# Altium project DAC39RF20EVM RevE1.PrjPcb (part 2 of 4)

## Sheet Power LDO N1p8V Analog.SchDoc: DAC Analog -1.8V
size 431 x 279 mm; Date: Not shown in title block; ApprovedBy: Not shown in title block; CheckedBy: Not shown in title block; Author: Not shown in title block; CompanyName: Not shown in title block; Engineer: Not shown in title block; Organization: Not shown in title block; Address1: Not shown in title block; Address2: Not shown in title block; Address3: Not shown in title block; Address4: Not shown in title block; DocumentNumber: 1; Revision: Use project parameter SCH_Rev; SheetNumber: 7; SheetTotal: 21; PageSetup: Record=PageOptions¦CenterHorizontal=True¦CenterVertical=True¦PrintScale=1.00¦XCorrection=1.00¦YCorrection=1.00¦PrintKind=0¦BorderSize=5000000¦LeftOffset=0¦BottomOffset=0¦Orientation=2¦PaperLength=1000¦PaperWidth=1000¦Scale=100¦PaperSource=15¦PrintQuality=600¦MediaType=1¦DitherType=10¦PaperKind=Letter¦PrintScaleMode=1
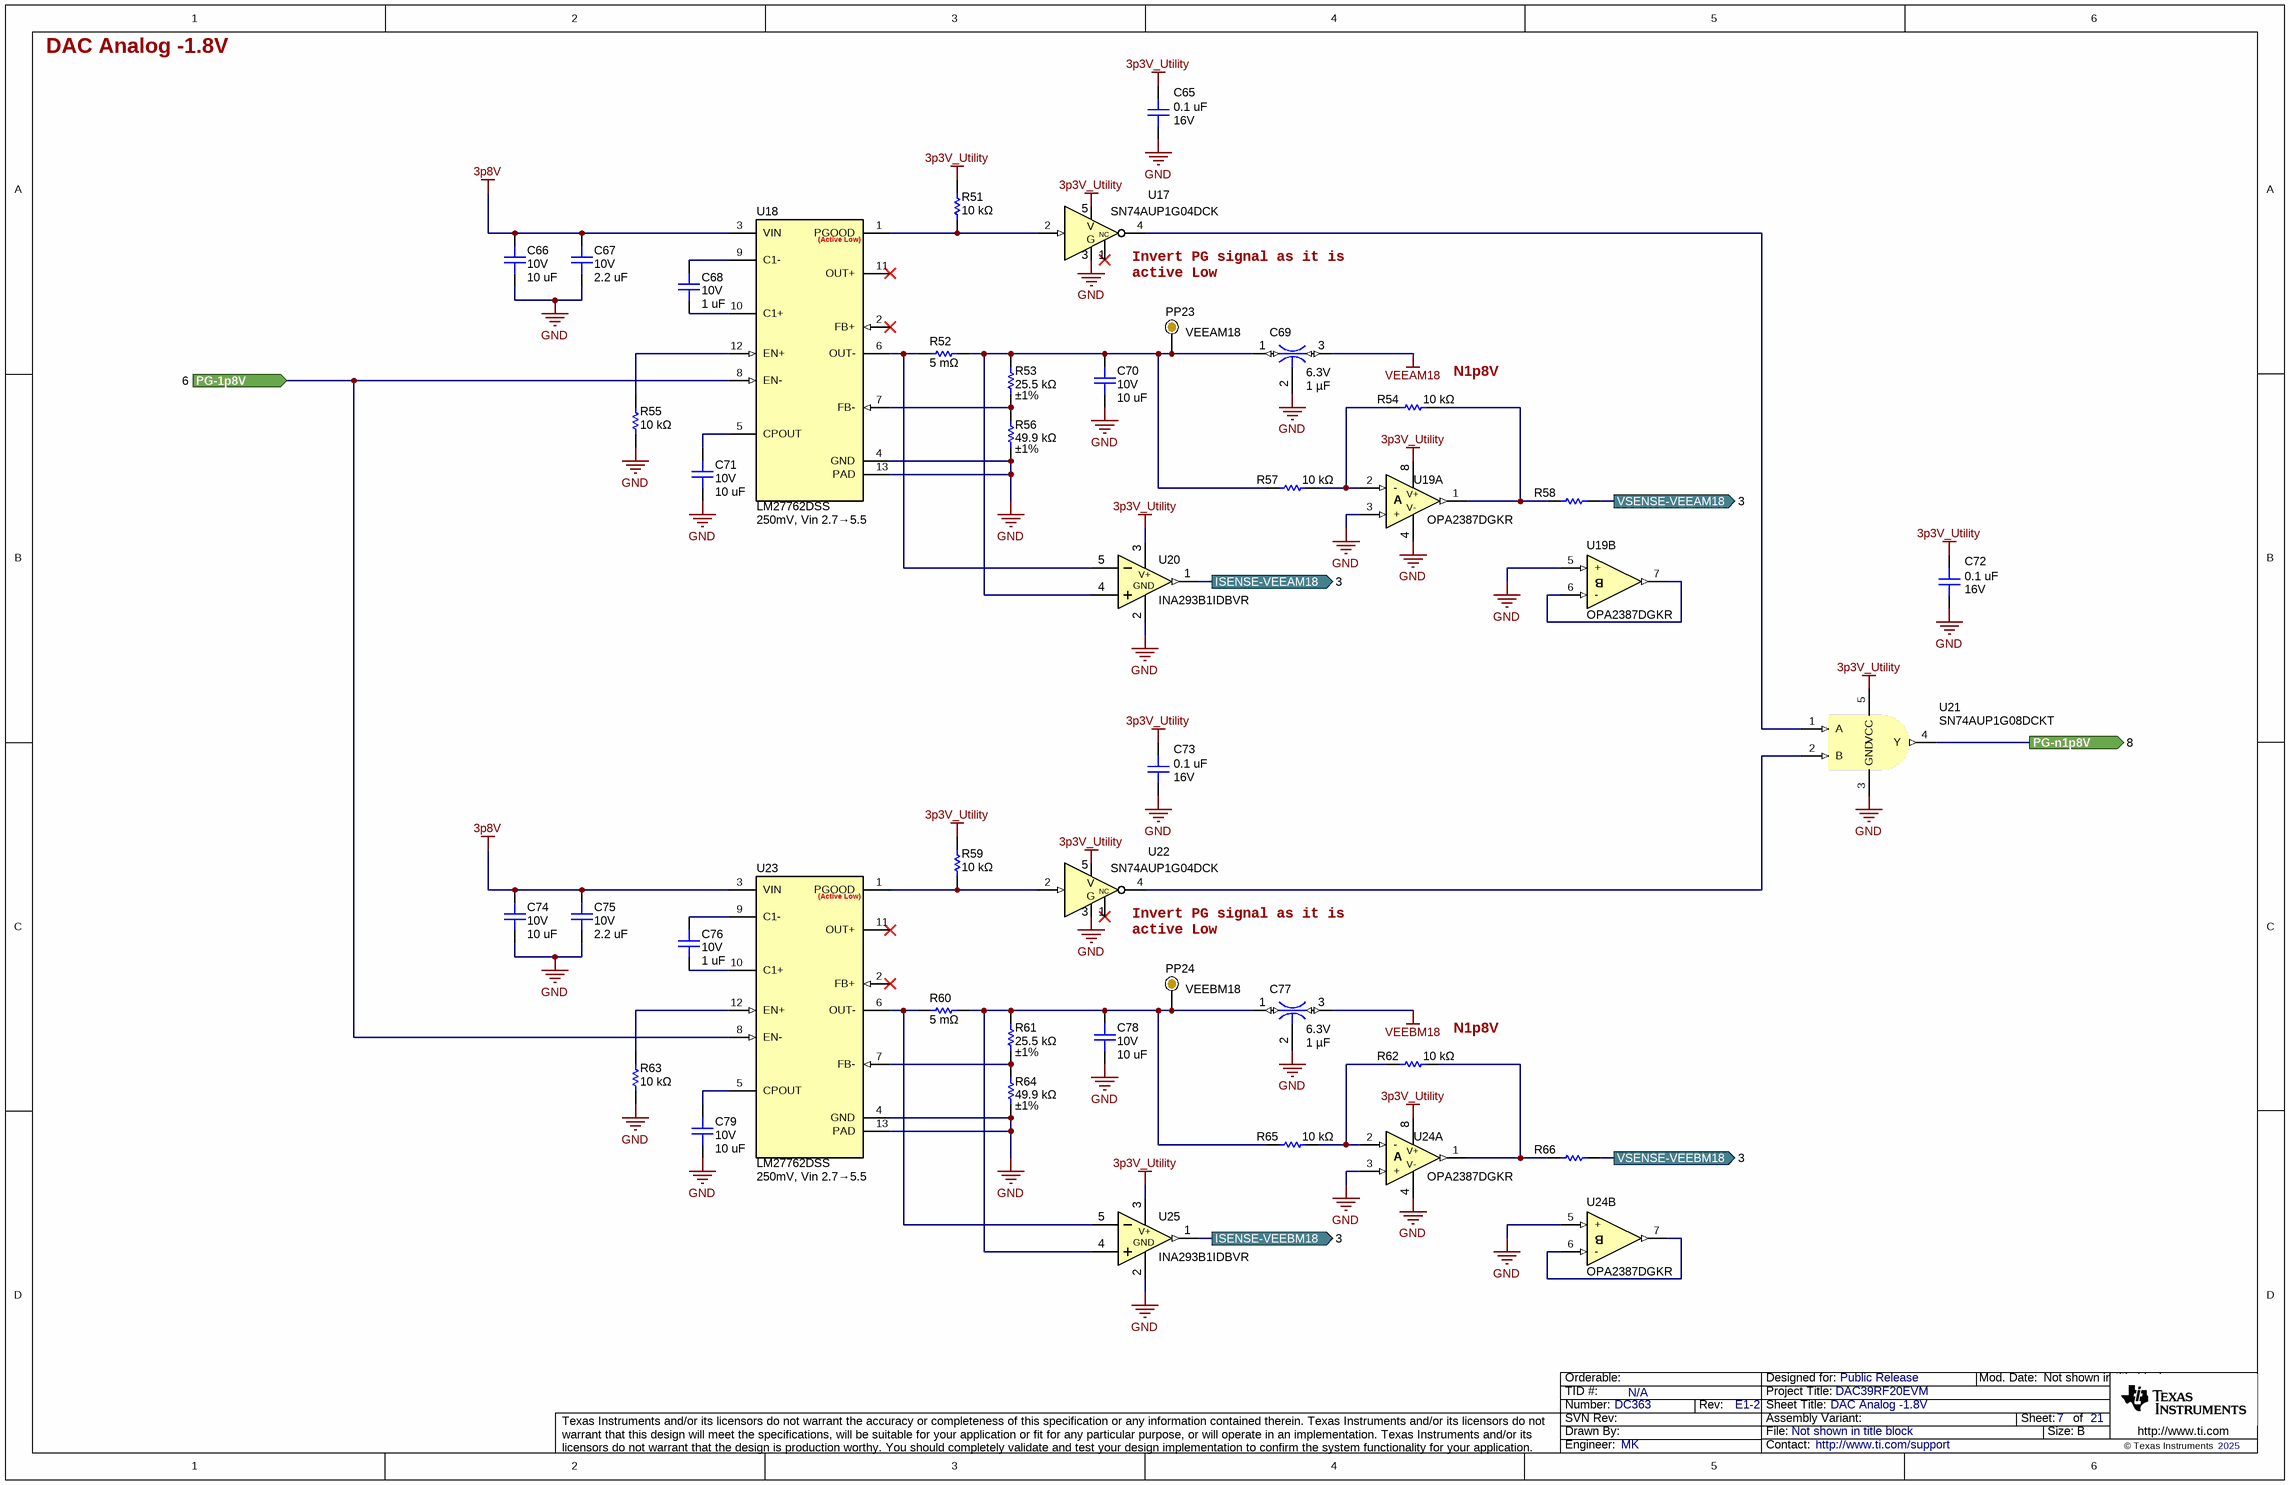
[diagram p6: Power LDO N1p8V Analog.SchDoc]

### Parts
C65  value 0.1 uF  Voltage - Rated: 16V  [0201_cap]  (hidden comment: GRM033Z71C104KE14J)
C66  value 10 uF  Voltage - Rated: 10V  [0603L_cap]  (hidden comment: 0603ZD106KAT2A)
C67  value 2.2 uF  Voltage - Rated: 10V  [0402L_cap]  (hidden comment: C1005X5R1A225K050BC)
C68  value 1 uF  Voltage - Rated: 10V  [0201_cap]  (hidden comment: GRM033R61A105ME44D)
C69  value 1 µF  Voltage - Rated: 6.3V  [NFM18PC]  (hidden comment: NFM18PC105R0J3D)
C70  value 10 uF  Voltage - Rated: 10V  [0603L_cap]  (hidden comment: 0603ZD106KAT2A)
C71  value 10 uF  Voltage - Rated: 10V  [0603L_cap]  (hidden comment: 0603ZD106KAT2A)
C72  value 0.1 uF  Voltage - Rated: 16V  [0201_cap]  (hidden comment: GRM033Z71C104KE14J)
C73  value 0.1 uF  Voltage - Rated: 16V  [0201_cap]  (hidden comment: GRM033Z71C104KE14J)
C74  value 10 uF  Voltage - Rated: 10V  [0603L_cap]  (hidden comment: 0603ZD106KAT2A)
C75  value 2.2 uF  Voltage - Rated: 10V  [0402L_cap]  (hidden comment: C1005X5R1A225K050BC)
C76  value 1 uF  Voltage - Rated: 10V  [0201_cap]  (hidden comment: GRM033R61A105ME44D)
C77  value 1 µF  Voltage - Rated: 6.3V  [NFM18PC]  (hidden comment: NFM18PC105R0J3D)
C78  value 10 uF  Voltage - Rated: 10V  [0603L_cap]  (hidden comment: 0603ZD106KAT2A)
C79  value 10 uF  Voltage - Rated: 10V  [0603L_cap]  (hidden comment: 0603ZD106KAT2A)
PP23  Text1: VEEAM18  [ProbePoint_TH_40mil]  (hidden comment: Probe Point)  (no BOM)
PP24  Text1: VEEBM18  [ProbePoint_TH_40mil]  (hidden comment: Probe Point)  (no BOM)
R51  value 10 kΩ  [0402L]  (hidden comment: ERJ-H2RF1002X)
R52  value 5 mΩ  [CCS0603FLxLxx]  (hidden comment: CSS0603FT5L00)
R53  value 25.5 kΩ  Tolerance: ±1%  [0402L]  (hidden comment: ERJ-2RKF2552X)
R54  value 10 kΩ  [0201]  (hidden comment: ERJ-U01F1002C)
R55  value 10 kΩ  [0402L]  (hidden comment: ERJ-H2RF1002X)
R56  value 49.9 kΩ  Tolerance: ±1%  [0402L]  (hidden comment: ERJ-2RKF4992X)
R57  value 10 kΩ  [0201]  (hidden comment: ERJ-U01F1002C)
R58  ERJ-1GNF1000C  [0201]  (value not drawn)
R59  value 10 kΩ  [0402L]  (hidden comment: ERJ-H2RF1002X)
R60  value 5 mΩ  [CCS0603FLxLxx]  (hidden comment: CSS0603FT5L00)
R61  value 25.5 kΩ  Tolerance: ±1%  [0402L]  (hidden comment: ERJ-2RKF2552X)
R62  value 10 kΩ  [0201]  (hidden comment: ERJ-U01F1002C)
R63  value 10 kΩ  [0402L]  (hidden comment: ERJ-H2RF1002X)
R64  value 49.9 kΩ  Tolerance: ±1%  [0402L]  (hidden comment: ERJ-2RKF4992X)
R65  value 10 kΩ  [0201]  (hidden comment: ERJ-U01F1002C)
R66  ERJ-1GNF1000C  [0201]  (value not drawn)
U17  SN74AUP1G04DCK  [DCK0005A]
U18  LM27762DSS  Text1: 250mV, Vin 2.7→5.5  [DSS0012B]
U19  OPA2387DGKR  [DGK0008A]  (parts A,B of 2)
U20  INA293B1IDBVR  [DBV0005A]
U21  SN74AUP1G08DCKT  [DCK0005A]
U22  SN74AUP1G04DCK  [DCK0005A]
U23  LM27762DSS  Text1: 250mV, Vin 2.7→5.5  [DSS0012B]
U24  OPA2387DGKR  [DGK0008A]  (parts A,B of 2)
U25  INA293B1IDBVR  [DBV0005A]

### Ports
ISENSE-VEEAM18 (out, see 3), ISENSE-VEEBM18 (out, see 3), PG-1p8V (in, see 6), PG-n1p8V (out, see 8), VSENSE-VEEAM18 (out, see 3), VSENSE-VEEBM18 (out, see 3)

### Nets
3p3V_Utility: C65.2 C72.2 C73.2 R51.2 R59.2 U17.5(VCC) U19.8(V+) U20.3(V+) U21.5(VCC) U22.5(VCC) U24.8(V+) U25.3(V+)
3p8V: C66.2 C67.2 C74.2 C75.2 U18.3(VIN) U23.3(VIN)
GND: C65.1 C66.1 C67.1 C69.2 C70.1 C71.1 C72.1 C73.1 C74.1 C75.1 C77.2 C78.1 C79.1 R55.1 R56.1 R63.1 R64.1 U17.3(GND) U18.4(GND) U18.13(PAD) U19.3(+) U19.4(GND) U19.5(+) U20.2(GND) U21.3(GND) U22.3(GND) U23.4(GND) U23.13(PAD) U24.3(+) U24.4(GND) U24.5(+) U25.2(GND)
VEEAM18: C69.3
VEEBM18: C77.3
ISENSE-VEEAM18: U20.1(OUT) ; port ISENSE-VEEAM18
ISENSE-VEEBM18: U25.1(OUT) ; port ISENSE-VEEBM18
PG-1p8V: U18.8(EN-) U23.8(EN-) ; port PG-1p8V
PG-n1p8V: U21.4(Y) ; port PG-n1p8V
VSENSE-VEEAM18: R58.2 ; port VSENSE-VEEAM18
VSENSE-VEEBM18: R66.2 ; port VSENSE-VEEBM18
NetC68_1: C68.1 U18.10(C1+)
NetC68_2: C68.2 U18.9(C1-)
NetC69_1: C69.1 C70.2 PP23.1 R52.2 R53.2 R57.1 U20.4(VIN+)
NetC71_2: C71.2 U18.5(CPOUT)
NetC76_1: C76.1 U23.10(C1+)
NetC76_2: C76.2 U23.9(C1-)
NetC77_1: C77.1 C78.2 PP24.1 R60.2 R61.2 R65.1 U25.4(VIN+)
NetC79_2: C79.2 U23.5(CPOUT)
NetR51_1: R51.1 U17.2(A) U18.1(PGOOD)
NetR52_1: R52.1 U18.6(OUT-) U20.5(VIN-)
NetR53_1: R53.1 R56.2 U18.7(FB-)
NetR54_1: R54.1 R57.2 U19.2(-)
NetR54_2: R54.2 R58.1 U19.1(A)
NetR55_2: R55.2 U18.12(EN+)
NetR59_1: R59.1 U22.2(A) U23.1(PGOOD)
NetR60_1: R60.1 U23.6(OUT-) U25.5(VIN-)
NetR61_1: R61.1 R64.2 U23.7(FB-)
NetR62_1: R62.1 R65.2 U24.2(-)
NetR62_2: R62.2 R66.1 U24.1(A)
NetR63_2: R63.2 U23.12(EN+)
NetU17_4: U17.4(Y) U21.1(A)
NetU19_6: U19.6(-) U19.7(B)
NetU21_2: U21.2(B) U22.4(Y)
NetU24_6: U24.6(-) U24.7(B)

Not connected (* = marked no-connect by the designer): U17 1(NC)*; U18 2(FB+)* 11(OUT+)*; U22 1(NC)*; U23 2(FB+)* 11(OUT+)*

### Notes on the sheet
- (near U17) Invert PG signal as it is active Low
- (near R54) N1p8V
- (near U22) Invert PG signal as it is active Low
- (near R62) N1p8V

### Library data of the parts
C65 C72 C73 = capcc09325: MLCC 0.1UF 16V X7R 0603; Manufacturer: Murata Electronics; SizeZ_mm: 0.33; SizeX_mm: 0.6; SizeY_mm: 0.3; CompType: Capacitor Ceramic; Tolerance: ±10%
C66 C70 C71 C74 C78 C79 = capcc03657: CAP CER 10UF 10V X5R 0603; Manufacturer: KYOCERA AVX; CompType: Capacitor Ceramic; Tolerance: ±10%; SizeX_mm: 1.6; SizeY_mm: 0.81; SizeZ_mm: 0.94
C67 C75 = capcc03112: CAP CER 2.2UF 10V X5R 0402; Manufacturer: TDK Corporation; CompType: Capacitor Ceramic; Tolerance: ±10%; SizeX_mm: 1; SizeY_mm: 0.5; SizeZ_mm: 0.55
C68 C76 = capcc09264: CAP CER 1UF 10V X5R 0201; Manufacturer: Murata Electronics; CompType: Capacitor Ceramic; Tolerance: ±20%; SizeX_mm: 0.6; SizeY_mm: 0.3; SizeZ_mm: 0.33
C69 C77 = dcp00009: CAP FEEDTHRU 1UF 20% 6.3V 0603; Manufacturer: Murata Electronics; CompType: Feed Thru Cap; Current: 4 A; DCR: 10 mΩ; SizeX_mm: 1.6; SizeY_mm: 0.8; SizeZ_mm: 0.7
PP23 PP24 = Probe Point: Probe Point that can be used in lue of a test point; UniqueID: cmp00025
R51 R55 R59 R63 = RSMD040200316: RES 10K OHM 1% 1/10W 0402; Manufacturer: Panasonic Electronic Components; CompType: Resistor SMD; Power (Watts): 0.1W, 1/10W; Temperature Coefficient: ±100ppm/°C; SizeX_mm: 1; SizeY_mm: 0.5; SizeZ_mm: 0.4
R52 R60 = OtherRs00006: RES 0.005 OHM 1% 1/3W 0603; Manufacturer: Stackpole Electronics Inc; CompType: Resistor SMD Sense; Power (Watts): 0.333W, 1/3W; Temperature Coefficient: ±50ppm/°C; SizeX_mm: 1.6; SizeY_mm: 0.8; SizeZ_mm: 0.65
R53 R61 = RSMD040201705: RES SMD 25.5K OHM 1% 1/10W 0402; Manufacturer: Panasonic Electronic Components; CompType: Resistor SMD; Power (Watts): 0.1W, 1/10W; Temperature Coefficient: ±100ppm/°C; SizeX_mm: 1; SizeY_mm: 0.5; SizeZ_mm: 0.4
R54 R57 R62 R65 = RSMD020100735: RES 10K OHM 1% 1/20W 0201 SMD; Manufacturer: Panasonic Electronic Components; CompType: Resistor SMD; Power (Watts): 0.05W, 1/20W; Temperature Coefficient: ±200ppm/°C
R56 R64 = RSMD040202910: RES SMD 49.9K OHM 1% 1/10W 0402; Manufacturer: Panasonic Electronic Components; CompType: Resistor SMD; Power (Watts): 0.1W, 1/10W; Temperature Coefficient: ±100ppm/°C; SizeX_mm: 1; SizeY_mm: 0.5; SizeZ_mm: 0.4
R58 R66 = RSMD020100289: RES SMD 100 OHM 1% 1/20W 0201; Manufacturer: Panasonic Electronic Components; Value: 100 Ω; CompType: Resistor SMD; Power (Watts): 0.05W, 1/20W; Temperature Coefficient: ±200ppm/°C
U17 U22 = cmp00128: Single Bus Inverting Buffer Gate; Manufacturer: Texas Instruments
U18 U23 = cmp00189: Low-Noise Positive- and Negative-Output Charge Pump With Integrated LDO; Manufacturer: Texas Instruments; CompType: Switcher
U19 U24 = OPA2387DGKR: Manufacturer: Texas Instruments; CompType: Op-amp
U20 U25 = INA293B1IDBV: INA293 High-Voltage, High Bandwidth, Unidirectional, 110-V Common-Mode, Current-Sense Amplifier, DBV0005A (SOT-23-5); Manufacturer: Texas Instruments; Alternate PartNumber: INA293B1IDBVT; SizeX_mm: 2.8; SizeArea_mm2: 8.12; SizeAreaWB_mm2: 14.82; AEC Qualified: N; AEC Category: Q200; SizeZ_mm: 1.45; CompType: IC; SizeY_mm: 2.9
U21 = cmp00268: SN74AUP1G08 Low-Power Single 2-Input Positive-AND Gate; Manufacturer: Texas Instruments

## Sheet Power LDO 0p8V Analog.SchDoc: DAC Analog 0.8V & 1V
size 431 x 279 mm; Date: Not shown in title block; ApprovedBy: Not shown in title block; CheckedBy: Not shown in title block; Author: Not shown in title block; CompanyName: Not shown in title block; Engineer: Not shown in title block; Organization: Not shown in title block; Address1: Not shown in title block; Address2: Not shown in title block; Address3: Not shown in title block; Address4: Not shown in title block; DocumentNumber: 1; Revision: Use project parameter SCH_Rev; SheetNumber: 8; SheetTotal: 21; PageSetup: Record=PageOptions¦CenterHorizontal=True¦CenterVertical=True¦PrintScale=1.00¦XCorrection=1.00¦YCorrection=1.00¦PrintKind=0¦BorderSize=5000000¦LeftOffset=0¦BottomOffset=0¦Orientation=2¦PaperLength=1000¦PaperWidth=1000¦Scale=100¦PaperSource=15¦PrintQuality=600¦MediaType=1¦DitherType=10¦PaperKind=Letter¦PrintScaleMode=1
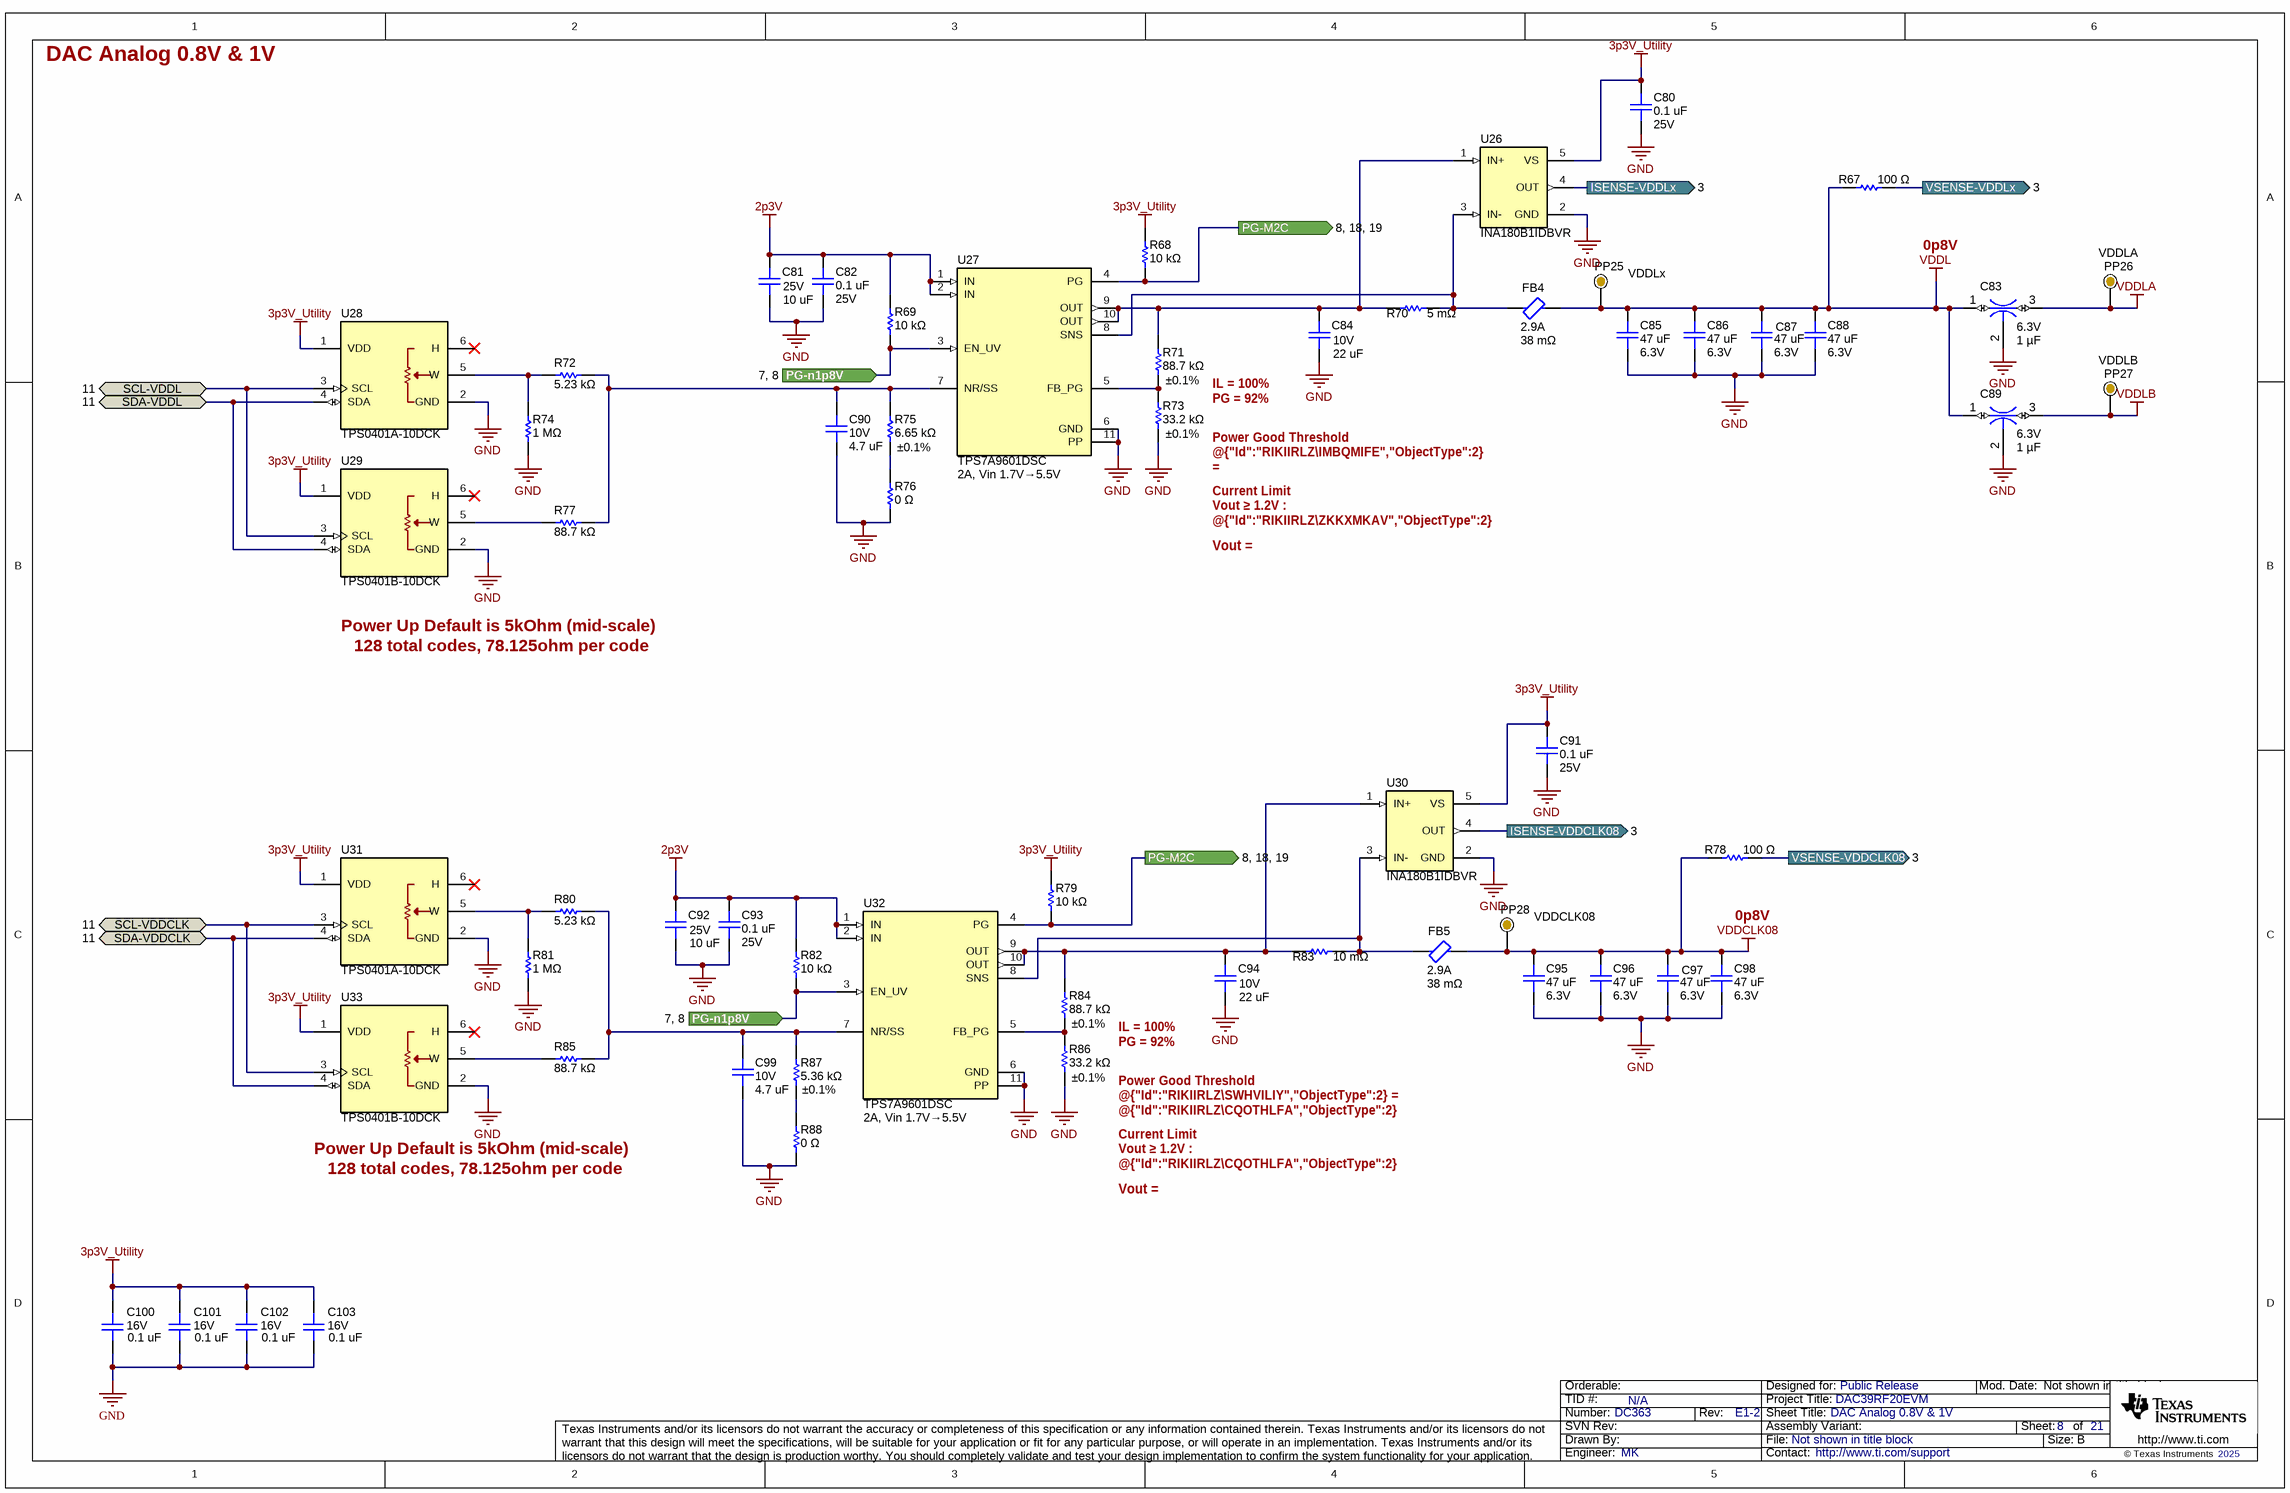
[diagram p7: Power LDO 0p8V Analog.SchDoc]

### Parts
C80  value 0.1 uF  Voltage - Rated: 25V  [0402L_cap]  (hidden comment: GRT155R71E104KE01J)
C81  value 10 uF  Voltage - Rated: 25V  [0805L_cap]  (hidden comment: C2012X7S1E106K125AC)
C82  value 0.1 uF  Voltage - Rated: 25V  [0402L_cap]  (hidden comment: GRT155R71E104KE01J)
C83  value 1 µF  Voltage - Rated: 6.3V  [NFM18PC]  (hidden comment: NFM18PC105R0J3D)
C84  value 22 uF  Voltage - Rated: 10V  [0805L_cap]  (hidden comment: C2012X7S1A226M125AC)
C85  value 47 uF  Voltage - Rated: 6.3V  [0603L_cap]  (hidden comment: GRM188R60J476ME15D)
C86  value 47 uF  Voltage - Rated: 6.3V  [0603L_cap]  (hidden comment: GRM188R60J476ME15D)
C87  value 47 uF  Voltage - Rated: 6.3V  [0603L_cap]  (hidden comment: GRM188R60J476ME15D)
C88  value 47 uF  Voltage - Rated: 6.3V  [0603L_cap]  (hidden comment: GRM188R60J476ME15D)
C89  value 1 µF  Voltage - Rated: 6.3V  [NFM18PC]  (hidden comment: NFM18PC105R0J3D)
C90  value 4.7 uF  Voltage - Rated: 10V  [0402L_cap]  (hidden comment: C1005X5R1A475K050BE)
C91  value 0.1 uF  Voltage - Rated: 25V  [0402L_cap]  (hidden comment: GRT155R71E104KE01J)
C92  value 10 uF  Voltage - Rated: 25V  [0805L_cap]  (hidden comment: C2012X7S1E106K125AC)
C93  value 0.1 uF  Voltage - Rated: 25V  [0402L_cap]  (hidden comment: GRT155R71E104KE01J)
C94  value 22 uF  Voltage - Rated: 10V  [0805L_cap]  (hidden comment: C2012X7S1A226M125AC)
C95  value 47 uF  Voltage - Rated: 6.3V  [0603L_cap]  (hidden comment: GRM188R60J476ME15D)
C96  value 47 uF  Voltage - Rated: 6.3V  [0603L_cap]  (hidden comment: GRM188R60J476ME15D)
C97  value 47 uF  Voltage - Rated: 6.3V  [0603L_cap]  (hidden comment: GRM188R60J476ME15D)
C98  value 47 uF  Voltage - Rated: 6.3V  [0603L_cap]  (hidden comment: GRM188R60J476ME15D)
C99  value 4.7 uF  Voltage - Rated: 10V  [0402L_cap]  (hidden comment: C1005X5R1A475K050BE)
C100  value 0.1 uF  Voltage - Rated: 16V  [0201_cap]  (hidden comment: C0603X5R1C104K030BC)
C101  value 0.1 uF  Voltage - Rated: 16V  [0201_cap]  (hidden comment: C0603X5R1C104K030BC)
C102  value 0.1 uF  Voltage - Rated: 16V  [0201_cap]  (hidden comment: C0603X5R1C104K030BC)
C103  value 0.1 uF  Voltage - Rated: 16V  [0201_cap]  (hidden comment: C0603X5R1C104K030BC)
FB4  Current: 2.9A  DCR: 38 mΩ  [1206L]  (hidden comment: BLM31KN601SN1L)
FB5  Current: 2.9A  DCR: 38 mΩ  [1206L]  (hidden comment: BLM31KN601SN1L)
PP25  Text1: VDDLx  [ProbePoint_TH_40mil]  (hidden comment: Probe Point)  (no BOM)
PP26  Text1: VDDLA  [ProbePoint_TH_40mil]  (hidden comment: Probe Point)  (no BOM)
PP27  Text1: VDDLB  [ProbePoint_TH_40mil]  (hidden comment: Probe Point)  (no BOM)
PP28  Text1: VDDCLK08  [ProbePoint_TH_40mil]  (hidden comment: Probe Point)  (no BOM)
R67  value 100 Ω  [0201]  (hidden comment: ERJ-1GNF1000C)
R68  value 10 kΩ  [0402L]  (hidden comment: ERJ-2RKF1002X)
R69  value 10 kΩ  [0402L]  (hidden comment: ERJ-2RKF1002X)
R70  value 5 mΩ  [CCS0603FLxLxx]  (hidden comment: CSS0603FT5L00)
R71  value 88.7 kΩ  Tolerance: ±0.1%  [0402L]  (hidden comment: ERA-2AEB8872X)
R72  value 5.23 kΩ  [0402L]  (hidden comment: ERA-2ARB5231X)
R73  value 33.2 kΩ  Tolerance: ±0.1%  [0402L]  (hidden comment: ERA-2AEB3322X)
R74  value 1 MΩ  [0402L]  (hidden comment: ERJ-PA2F1004X)
R75  value 6.65 kΩ  Tolerance: ±0.1%  [0402L]  (hidden comment: ERA-2AEB6651X)
R76  value 0 Ω  [0402L]  (hidden comment: ERJ-U020R00X)
R77  value 88.7 kΩ  [0402L]  (hidden comment: ERA-2AEB8872X)
R78  value 100 Ω  [0201]  (hidden comment: ERJ-1GNF1000C)
R79  value 10 kΩ  [0402L]  (hidden comment: ERJ-2RKF1002X)
R80  value 5.23 kΩ  [0402L]  (hidden comment: ERA-2ARB5231X)
R81  value 1 MΩ  [0402L]  (hidden comment: ERJ-PA2F1004X)
R82  value 10 kΩ  [0402L]  (hidden comment: ERJ-2RKF1002X)
R83  value 10 mΩ  [CCS0603FLxLxx]  (hidden comment: CSS0603FT10L0)
R84  value 88.7 kΩ  Tolerance: ±0.1%  [0402L]  (hidden comment: ERA-2AEB8872X)
R85  value 88.7 kΩ  [0402L]  (hidden comment: ERA-2AEB8872X)
R86  value 33.2 kΩ  Tolerance: ±0.1%  [0402L]  (hidden comment: ERA-2AEB3322X)
R87  value 5.36 kΩ  Tolerance: ±0.1%  [0402L]  (hidden comment: ERA-2AEB5361X)
R88  value 0 Ω  [0402L]  (hidden comment: ERJ-U020R00X)
U26  INA180B1IDBVR  [DBV0005A]
U27  TPS7A9601DSC  Text1: 2A, Vin 1.7V→5.5V  [DRC0010J]
U28  TPS0401A-10DCK  [DCK0006A]
U29  TPS0401B-10DCK  [DCK0006A]
U30  INA180B1IDBVR  [DBV0005A]
U31  TPS0401A-10DCK  [DCK0006A]
U32  TPS7A9601DSC  Text1: 2A, Vin 1.7V→5.5V  [DRC0010J]
U33  TPS0401B-10DCK  [DCK0006A]

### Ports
ISENSE-VDDCLK08 (out, see 3), ISENSE-VDDLx (out, see 3), PG-M2C (out, see 8, 18, 19), PG-n1p8V (in, see 7, 8), SCL-VDDCLK (bidir, see 11), SCL-VDDL (bidir, see 11), SDA-VDDCLK (bidir, see 11), SDA-VDDL (bidir, see 11), VSENSE-VDDCLK08 (out, see 3), VSENSE-VDDLx (out, see 3)

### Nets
2p3V: C81.2 C82.2 C92.2 C93.2 R69.2 R82.2 U27.1(IN) U27.2(IN) U32.1(IN) U32.2(IN)
3p3V_Utility: C80.2 C91.2 C100.1 C101.1 C102.1 C103.1 R68.2 R79.2 U26.5(VS) U28.1(VDD) U29.1(VDD) U30.5(VS) U31.1(VDD) U33.1(VDD)
GND: C80.1 C81.1 C82.1 C83.2 C84.1 C85.1 C86.1 C87.1 C88.1 C89.2 C90.1 C91.1 C92.1 C93.1 C94.1 C95.1 C96.1 C97.1 C98.1 C99.1 C100.2 C101.2 C102.2 C103.2 R73.1 R74.2 R76.1 R81.2 R86.1 R88.1 U26.2(GND) U27.6(GND) U27.11(PP) U28.2(GND) U29.2(GND) U30.2(GND) U31.2(GND) U32.6(GND) U32.11(PP) U33.2(GND)
VDDCLK08: C95.2 C96.2 C97.2 C98.2 FB5.2 PP28.1 R78.1
VDDL: C83.1 C85.2 C86.2 C87.2 C88.2 C89.1 FB4.2 PP25.1 R67.1
VDDLA: C83.3 PP26.1
VDDLB: C89.3 PP27.1
ISENSE-VDDCLK08: U30.4(OUT) ; port ISENSE-VDDCLK08
ISENSE-VDDLx: U26.4(OUT) ; port ISENSE-VDDLx
PG-M2C: R68.1 R79.1 U27.4(PG) U32.4(PG) ; port PG-M2C
PG-n1p8V: R69.1 R82.1 U27.3(EN_UV) U32.3(EN_UV) ; port PG-n1p8V
SCL-VDDCLK: U31.3(SCL) U33.3(SCL) ; port SCL-VDDCLK
SCL-VDDL: U28.3(SCL) U29.3(SCL) ; port SCL-VDDL
SDA-VDDCLK: U31.4(SDA) U33.4(SDA) ; port SDA-VDDCLK
SDA-VDDL: U28.4(SDA) U29.4(SDA) ; port SDA-VDDL
VSENSE-VDDCLK08: R78.2 ; port VSENSE-VDDCLK08
VSENSE-VDDLx: R67.2 ; port VSENSE-VDDLx
NetC84_2: C84.2 R70.1 R71.2 U26.1(IN+) U27.9(OUT) U27.10(OUT)
NetC90_2: C90.2 R72.1 R75.2 R77.2 U27.7(NR/SS)
NetC94_2: C94.2 R83.1 R84.2 U30.1(IN+) U32.9(OUT) U32.10(OUT)
NetC99_2: C99.2 R80.1 R85.2 R87.2 U32.7(NR/SS)
NetFB4_1: FB4.1 R70.2 U26.3(IN-) U27.8(SNS)
NetFB5_1: FB5.1 R83.2 U30.3(IN-) U32.8(SNS)
NetR71_1: R71.1 R73.2 U27.5(FB_PG)
NetR72_2: R72.2 R74.1 U28.5(W)
NetR75_1: R75.1 R76.2
NetR77_1: R77.1 U29.5(W)
NetR80_2: R80.2 R81.1 U31.5(W)
NetR84_1: R84.1 R86.2 U32.5(FB_PG)
NetR85_1: R85.1 U33.5(W)
NetR87_1: R87.1 R88.2

Not connected (* = marked no-connect by the designer): U28 6(H)*; U29 6(H)*; U31 6(H)*; U33 6(H)*

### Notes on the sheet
- 0p8V
- IL = 100%
  PG = 92%
- Power Good Threshold
  @{"Id":"RIKIIRLZ\IMBQMIFE","ObjectType":2} = @{"Id":"RIKIIRLZ\ZKKXMKAV","ObjectType":2} * (VOUT/0.2*K-1)
  K = PG % Threshold
- Current Limit
  Vout ≥ 1.2V :    @{"Id":"RIKIIRLZ\ZKKXMKAV","ObjectType":2} = 0.2V/16µA = 12.4kΩ
  0.4V≤Vout<1.2V : @{"Id":"RIKIIRLZ\ZKKXMKAV","ObjectType":2}  = 0.2V/6µA = 33.2k Ω
- Vout = (@{"Id":"RIKIIRLZ\SPHKWSGB","ObjectType":2} + @{"Id":"RIKIIRLZ\QDQZCBMS","ObjectType":2}) *150µA
- Power Up Default is 5kOhm (mid-scale)
- 128 total codes, 78.125ohm per code
- Power Good Threshold
  @{"Id":"RIKIIRLZ\SWHVILIY","ObjectType":2} = @{"Id":"RIKIIRLZ\CQOTHLFA","ObjectType":2} * (VOUT/0.2*K-1)
  K = PG % Threshold
- Current Limit
  Vout ≥ 1.2V :    @{"Id":"RIKIIRLZ\CQOTHLFA","ObjectType":2} = 0.2V/16µA = 12.4kΩ
  0.4V≤Vout<1.2V : @{"Id":"RIKIIRLZ\CQOTHLFA","ObjectType":2}  = 0.2V/6µA = 33.2k Ω
- Vout = (@{"Id":"RIKIIRLZ\LLIXUJIG","ObjectType":2} + @{"Id":"RIKIIRLZ\LXJCPRKC","ObjectType":2}) *150µA

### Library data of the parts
C80 C82 C91 C93 = capcc09401: CAP CER 0.1UF 25V X7R 0402; Manufacturer: Murata; CompType: Capacitor Ceramic; Tolerance: ±10%; SizeX_mm: 1; SizeY_mm: 0.5; SizeZ_mm: 0.7
C81 C92 = capcc03511: CAP CER 10UF 25V X7S 0805; Manufacturer: TDK Corporation; CompType: Capacitor Ceramic; Tolerance: ±10%; SizeX_mm: 2; SizeY_mm: 1.25; SizeZ_mm: 1.5
C83 C89 = dcp00009: as C69 on sheet Power LDO N1p8V Analog
C84 C94 = capcc09395: CAP CER 22UF 10V X7S 0805; Manufacturer: TDK Corporation; CompType: Capacitor Ceramic; Tolerance: ±20%; SizeX_mm: 2; SizeY_mm: 1.25; SizeZ_mm: 1.45
C85-C88 C95-C98 = GRM188R60J476ME15D: CAP CER 47UF 6.3V X5R 0603; Manufacturer: Murata; CompType: Capacitor Ceramic; Tolerance: ±20%; SizeX_mm: 1.6; SizeY_mm: 0.81; SizeZ_mm: 0.9
C90 C99 = capcc03139: CAP CER 4.7UF 10V X5R 0402; Manufacturer: TDK Corporation; CompType: Capacitor Ceramic; Tolerance: ±10%; SizeX_mm: 1; SizeY_mm: 0.5; SizeZ_mm: 0.7
C100-C103 = capcc01389: CAP CER 0.1UF 16V X5R 0201; Manufacturer: TDK Corporation; SizeZ_mm: 0.33; SizeY_mm: 0.3; CompType: Capacitor Ceramic; SizeX_mm: 0.6; Tolerance: ±10%
FB4 FB5 = dcp00613: FERRITE BEAD 600 OHM 1206 1LN; Manufacturer: Murata Electronics; Impedance: 600 Ω
PP25-PP28 = Probe Point: as PP23 on sheet Power LDO N1p8V Analog
R67 R78 = RSMD020100289: RES SMD 100 OHM 1% 1/20W 0201; Manufacturer: Panasonic Electronic Components; CompType: Resistor SMD; Power (Watts): 0.05W, 1/20W; Temperature Coefficient: ±200ppm/°C
R68 R69 R79 R82 = RSMD040200314: RES SMD 10K OHM 1% 1/10W 0402; Manufacturer: Panasonic Electronic Components; CompType: Resistor SMD; Power (Watts): 0.1W, 1/10W; Temperature Coefficient: ±100ppm/°C; SizeX_mm: 1; SizeY_mm: 0.5; SizeZ_mm: 0.4
R70 = OtherRs00006: as R52 on sheet Power LDO N1p8V Analog
R71 R77 R84 R85 = RSMD040203878: RES SMD 88.7KOHM 0.1% 1/16W 0402; Manufacturer: Panasonic Electronic Components; CompType: Resistor SMD; Power (Watts): 0.063W, 1/16W; Temperature Coefficient: ±25ppm/°C; SizeX_mm: 1; SizeY_mm: 0.5; SizeZ_mm: 0.4
R72 R80 = RSMD040202949: RES SMD 5.23KOHM 0.1% 1/16W 0402; Manufacturer: Panasonic Electronic Components; CompType: Resistor SMD; Power (Watts): 0.063W, 1/16W; Temperature Coefficient: ±10ppm/°C; SizeX_mm: 1; SizeY_mm: 0.5; SizeZ_mm: 0.4
R73 R86 = RSMD040202236: RES SMD 33.2KOHM 0.1% 1/16W 0402; Manufacturer: Panasonic Electronic Components; CompType: Resistor SMD; Power (Watts): 0.063W, 1/16W; Temperature Coefficient: ±25ppm/°C; SizeX_mm: 1; SizeY_mm: 0.5; SizeZ_mm: 0.4
R74 R81 = RSMD040200022: RES SMD 1M OHM 1% 1/5W 0402; Manufacturer: Panasonic Electronic Components; CompType: Resistor SMD; Power (Watts): 0.2W, 1/5W; Temperature Coefficient: ±100ppm/°C; SizeX_mm: 1; SizeY_mm: 0.5; SizeZ_mm: 0.4
R75 = RSMD040203275: RES SMD 6.65KOHM 0.1% 1/16W 0402; Manufacturer: Panasonic Electronic Components; CompType: Resistor SMD; Power (Watts): 0.063W, 1/16W; Temperature Coefficient: ±25ppm/°C; SizeX_mm: 1; SizeY_mm: 0.5; SizeZ_mm: 0.4
R76 R88 = RSMD040200004: RES 0 OHM JUMPER 0402 SMD; Manufacturer: Panasonic Electronic Components; CompType: Resistor SMD; Power (Watts): 0.1W, 1/10W; Temperature Coefficient: -100/ +600ppm/°C; SizeX_mm: 1; SizeY_mm: 0.5; SizeZ_mm: 0.4
R83 = OtherRs00003: RES 0.01 OHM 1% 1/3W 0603; Manufacturer: Stackpole Electronics Inc; CompType: Resistor SMD Sense; Power (Watts): 0.333W, 1/3W; Temperature Coefficient: ±50ppm/°C; SizeX_mm: 1.6; SizeY_mm: 0.8; SizeZ_mm: 0.65
R87 = RSMD040202954: RES SMD 5.36KOHM 0.1% 1/16W 0402; Manufacturer: Panasonic Electronic Components; CompType: Resistor SMD; Power (Watts): 0.063W, 1/16W; Temperature Coefficient: ±25ppm/°C; SizeX_mm: 1; SizeY_mm: 0.5; SizeZ_mm: 0.4
U26 U30 = INA180B1IDBVR: 26V, 350kHz current sense amplifier; Manufacturer: Texas Instruments; Alt PartNumber: INA180B1IDBVT; CompType: Current Amplifier
U27 U32 = cmp00446: 2-A, ultra-low noise ultra-high PSRR RF voltage regulator; PartNumber: TPS7A9601DSCR; Manufacturer: Texas Instruments; CompType: LDO
U28 U31 = cmp00230: 128-tap single-channel digital potentiometer (digipot) with I2C interface (address 0101110); Alternate PartNumber: TPL0401A-10DCKT; Manufacturer: Texas Instruments; SymbolCreator: Altium; SizeArea_mm2: 4.2; U/M: EA; SizeAreaWB_mm2: 9.3
U29 U33 = cmp00231: 128-tap single-channel digital potentiometer (digipot) with I2C interface (address 0111110); Alternate PartNumber: TPL0401A-10DCKT; Manufacturer: Texas Instruments; SymbolCreator: Altium; SizeArea_mm2: 4.2; U/M: EA; SizeAreaWB_mm2: 9.3

## Sheet Power LMK.SchDoc: LMK 3.3V Power
size 431 x 279 mm; Date: Not shown in title block; ApprovedBy: Not shown in title block; CheckedBy: Not shown in title block; Author: Not shown in title block; CompanyName: Not shown in title block; Engineer: Not shown in title block; Organization: Not shown in title block; Address1: Not shown in title block; Address2: Not shown in title block; Address3: Not shown in title block; Address4: Not shown in title block; DocumentNumber: 1; Revision: Use project parameter SCH_Rev; SheetNumber: 9; SheetTotal: 21; PageSetup: Record=PageOptions¦CenterHorizontal=True¦CenterVertical=True¦PrintScale=1.00¦XCorrection=1.00¦YCorrection=1.00¦PrintKind=0¦BorderSize=5000000¦LeftOffset=0¦BottomOffset=0¦Orientation=2¦PaperLength=1000¦PaperWidth=1000¦Scale=100¦PaperSource=15¦PrintQuality=600¦MediaType=1¦DitherType=10¦PaperKind=Letter¦PrintScaleMode=1
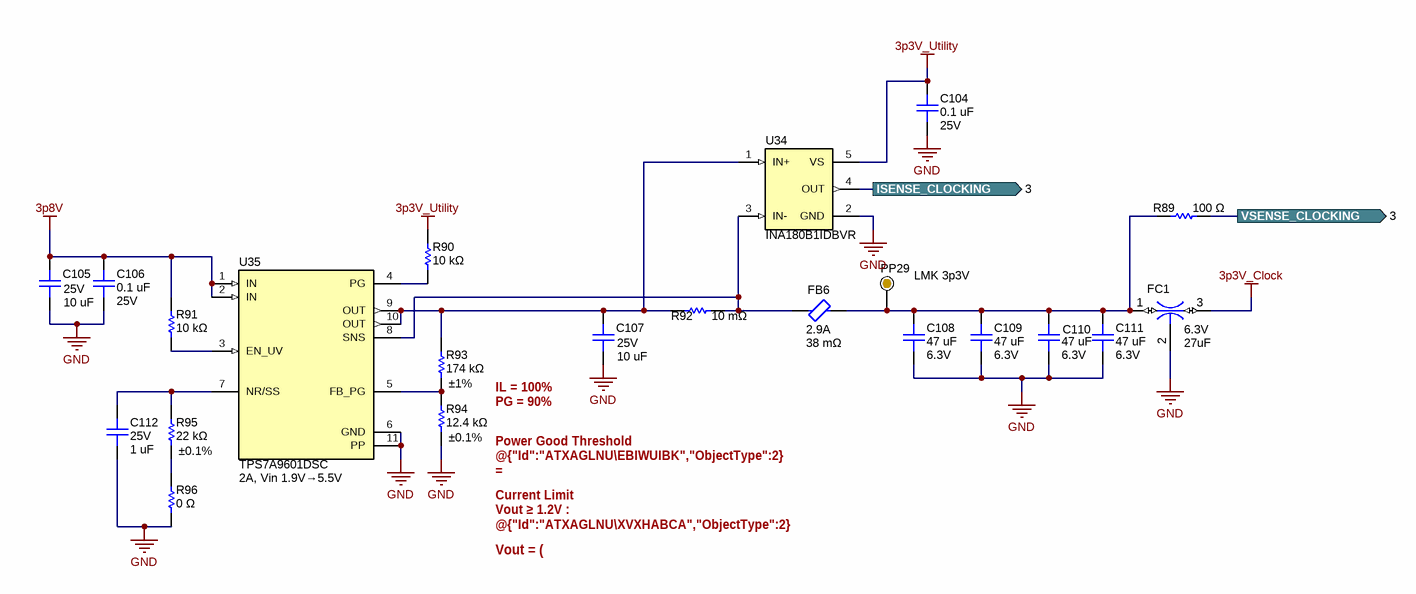
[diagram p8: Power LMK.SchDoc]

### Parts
C104  value 0.1 uF  Voltage - Rated: 25V  [0402L_cap]  (hidden comment: GRT155R71E104KE01J)
C105  value 10 uF  Voltage - Rated: 25V  [0805L_cap]  (hidden comment: C2012X7S1E106K125AC)
C106  value 0.1 uF  Voltage - Rated: 25V  [0402L_cap]  (hidden comment: GRT155R71E104KE01J)
C107  value 10 uF  Voltage - Rated: 25V  [0805L_cap]  (hidden comment: C2012X7S1E106K125AC)
C108  value 47 uF  Voltage - Rated: 6.3V  [0603L_cap]  (hidden comment: GRM188R60J476ME15D)
C109  value 47 uF  Voltage - Rated: 6.3V  [0603L_cap]  (hidden comment: GRM188R60J476ME15D)
C110  value 47 uF  Voltage - Rated: 6.3V  [0603L_cap]  (hidden comment: GRM188R60J476ME15D)
C111  value 47 uF  Voltage - Rated: 6.3V  [0603L_cap]  (hidden comment: GRM188R60J476ME15D)
C112  value 1 uF  Voltage - Rated: 25V  [0402L_cap]  (hidden comment: C1005X5R1E105K050BC)
FB6  Current: 2.9A  DCR: 38 mΩ  [1206L]  (hidden comment: BLM31KN601SN1L)
FC1  value 27uF  Voltage - Rated: 6.3V  [NFM31PC]  (hidden comment: dcp00001)
PP29  Text1: LMK 3p3V  [ProbePoint_TH_40mil]  (hidden comment: Probe Point)  (no BOM)
R89  value 100 Ω  [0201]  (hidden comment: ERJ-1GNF1000C)
R90  value 10 kΩ  [0402L]  (hidden comment: ERJ-2RKF1002X)
R91  value 10 kΩ  [0402L]  (hidden comment: ERJ-2RKF1002X)
R92  value 10 mΩ  [CCS0603FLxLxx]  (hidden comment: CSS0603FT10L0)
R93  value 174 kΩ  Tolerance: ±1%  [0402L]  (hidden comment: ERJ-2RKF1743X)
R94  value 12.4 kΩ  Tolerance: ±0.1%  [0402L]  (hidden comment: ERA-2AEB1242X)
R95  value 22 kΩ  Tolerance: ±0.1%  [0402L]  (hidden comment: ERA-2AEB223X)
R96  value 0 Ω  [0402L]  (hidden comment: ERJ-U020R00X)
U34  INA180B1IDBVR  [DBV0005A]
U35  TPS7A9601DSC  Text1: 2A, Vin 1.9V→5.5V  [DRC0010J]

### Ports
ISENSE_CLOCKING (out, see 3), VSENSE_CLOCKING (out, see 3)

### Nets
3p3V_Clock: FC1.3
3p3V_Utility: C104.2 R90.2 U34.5(VS)
3p8V: C105.2 C106.2 R91.2 U35.1(IN) U35.2(IN)
GND: C104.1 C105.1 C106.1 C107.1 C108.1 C109.1 C110.1 C111.1 C112.1 FC1.2 R94.1 R96.1 U34.2(GND) U35.6(GND) U35.11(PP)
ISENSE_CLOCKING: U34.4(OUT) ; port ISENSE_CLOCKING
VSENSE_CLOCKING: R89.2 ; port VSENSE_CLOCKING
NetC107_2: C107.2 R92.1 R93.2 U34.1(IN+) U35.9(OUT) U35.10(OUT)
NetC108_2: C108.2 C109.2 C110.2 C111.2 FB6.2 FC1.1 PP29.1 R89.1
NetC112_2: C112.2 R95.2 U35.7(NR/SS)
NetFB6_1: FB6.1 R92.2 U34.3(IN-) U35.8(SNS)
NetR90_1: R90.1 U35.4(PG)
NetR91_1: R91.1 U35.3(EN_UV)
NetR93_1: R93.1 R94.2 U35.5(FB_PG)
NetR95_1: R95.1 R96.2

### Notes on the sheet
- IL = 100%
  PG = 90%
- Power Good Threshold
  @{"Id":"ATXAGLNU\EBIWUIBK","ObjectType":2} = @{"Id":"ATXAGLNU\XVXHABCA","ObjectType":2} * (VOUT/0.2*K-1)
  K = PG % Threshold
- Current Limit
  Vout ≥ 1.2V :    @{"Id":"ATXAGLNU\XVXHABCA","ObjectType":2} = 0.2V/16µA = 12.4kΩ
  0.4V≤Vout<1.2V : @{"Id":"ATXAGLNU\XVXHABCA","ObjectType":2}  = 0.2V/6µA = 33.2k Ω
- Vout = ( @{"Id":"ATXAGLNU\PEIXZBPC","ObjectType":2}+ @{"Id":"ATXAGLNU\ZHITUAEH","ObjectType":2}) *150µA

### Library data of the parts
C104 C106 = capcc09401: as C80 on sheet Power LDO 0p8V Analog
C105 C107 = capcc03511: as C81 on sheet Power LDO 0p8V Analog
C108-C111 = GRM188R60J476ME15D: as C85-C88 on sheet Power LDO 0p8V Analog
C112 = CeramicCap: CAP CER 1UF 25V X5R 0402; Manufacturer: TDK Corporation; UniqueID: capcc02750; CompType: Capacitor Ceramic; Tolerance: ±10%; SizeX_mm: 1; SizeY_mm: 0.5; SizeZ_mm: 0.55
FB6 = dcp00613: as FB4 on sheet Power LDO 0p8V Analog
FC1 = dcp00001: Feed through capactior 27uF; PartNumber: NFM31PC276B0J3L; Manufacturer: Murata; CompType: Feed Thru Cap; Tolerance: ±20%; SizeX_mm: 3.2; SizeY_mm: 1.6; SizeZ_mm: 1.5; Current: 6A; DCR: 5 mΩ
PP29 = Probe Point: as PP23 on sheet Power LDO N1p8V Analog
R89 = RSMD020100289: as R67 on sheet Power LDO 0p8V Analog
R90 R91 = RSMD040200314: as R68 on sheet Power LDO 0p8V Analog
R92 = OtherRs00003: as R83 on sheet Power LDO 0p8V Analog
R93 = RSMD040200995: RES SMD 174K OHM 1% 1/10W 0402; Manufacturer: Panasonic Electronic Components; CompType: Resistor SMD; Power (Watts): 0.1W, 1/10W; Temperature Coefficient: ±100ppm/°C; SizeX_mm: 1; SizeY_mm: 0.5; SizeZ_mm: 0.4
R94 = RSMD040200551: RES SMD 12.4KOHM 0.1% 1/16W 0402; Manufacturer: Panasonic Electronic Components; CompType: Resistor SMD; Power (Watts): 0.063W, 1/16W; Temperature Coefficient: ±25ppm/°C; SizeX_mm: 1; SizeY_mm: 0.5; SizeZ_mm: 0.4
R95 = RSMD040201463: RES SMD 22K OHM 0.1% 1/16W 0402; Manufacturer: Panasonic Electronic Components; CompType: Resistor SMD; Power (Watts): 0.063W, 1/16W; Temperature Coefficient: ±25ppm/°C; SizeX_mm: 1; SizeY_mm: 0.5; SizeZ_mm: 0.4
R96 = RSMD040200004: as R76 on sheet Power LDO 0p8V Analog
U34 = INA180B1IDBVR: as U26 on sheet Power LDO 0p8V Analog
U35 = cmp00446: as U27 on sheet Power LDO 0p8V Analog

## Sheet USB Control FTDI.SchDoc: FTDI Control
size 431 x 279 mm; Date: Not shown in title block; ApprovedBy: Not shown in title block; CheckedBy: Not shown in title block; Author: Not shown in title block; CompanyName: Not shown in title block; Engineer: Not shown in title block; Organization: Not shown in title block; Address1: Not shown in title block; Address2: Not shown in title block; Address3: Not shown in title block; Address4: Not shown in title block; DocumentNumber: 1; Revision: Use project parameter SCH_Rev; SheetNumber: 10; SheetTotal: 21; PageSetup: Record=PageOptions¦CenterHorizontal=True¦CenterVertical=True¦PrintScale=1.00¦XCorrection=1.00¦YCorrection=1.00¦PrintKind=0¦BorderSize=5000000¦LeftOffset=0¦BottomOffset=0¦Orientation=2¦PaperLength=1000¦PaperWidth=1000¦Scale=100¦PaperSource=15¦PrintQuality=600¦MediaType=1¦DitherType=10¦PaperKind=Letter¦PrintScaleMode=1
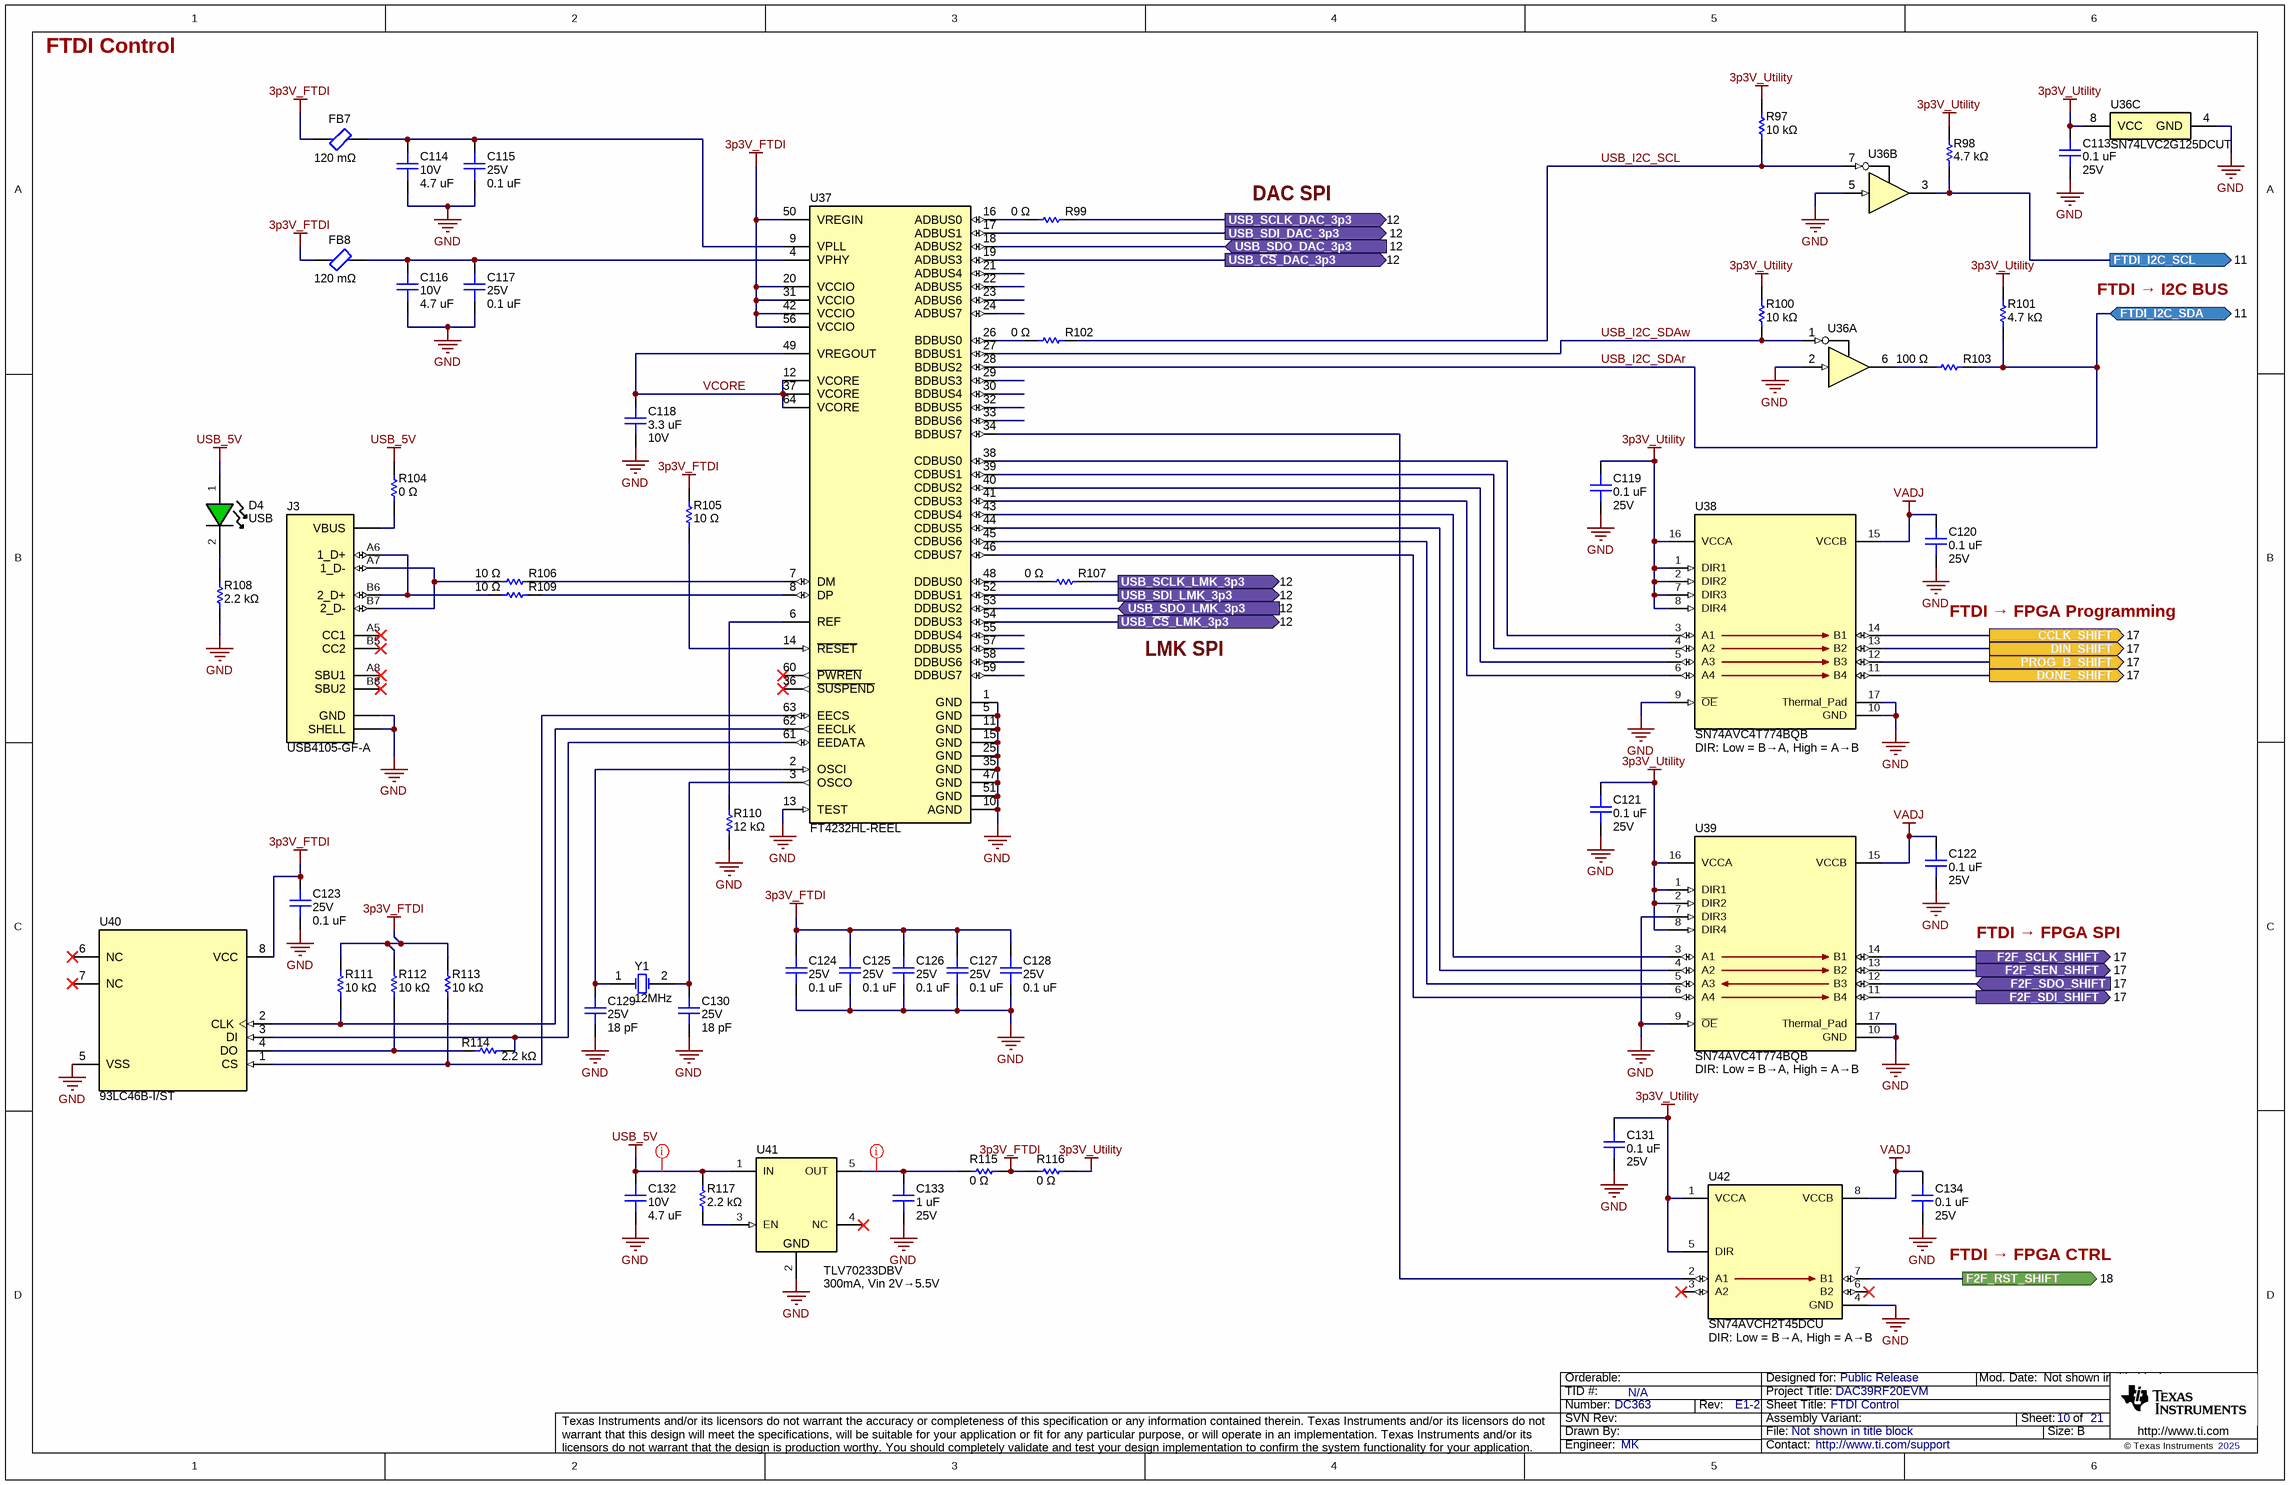
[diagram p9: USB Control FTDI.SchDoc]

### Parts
C113  value 0.1 uF  Voltage - Rated: 25V  [0402L_cap]  (hidden comment: GRT155R71E104KE01J)
C114  value 4.7 uF  Voltage - Rated: 10V  [0402L_cap]  (hidden comment: C1005X5R1A475K050BC)
C115  value 0.1 uF  Voltage - Rated: 25V  [0402L_cap]  (hidden comment: 04023D104KAT2A)
C116  value 4.7 uF  Voltage - Rated: 10V  [0402L_cap]  (hidden comment: C1005X5R1A475K050BC)
C117  value 0.1 uF  Voltage - Rated: 25V  [0402L_cap]  (hidden comment: 04023D104KAT2A)
C118  value 3.3 uF  Voltage - Rated: 10V  [0603L_cap]  (hidden comment: CGA3E1X5R1A335K080AC)
C119  value 0.1 uF  Voltage - Rated: 25V  [0402L_cap]  (hidden comment: GRT155R71E104KE01J)
C120  value 0.1 uF  Voltage - Rated: 25V  [0402L_cap]  (hidden comment: GRT155R71E104KE01J)
C121  value 0.1 uF  Voltage - Rated: 25V  [0402L_cap]  (hidden comment: GRT155R71E104KE01J)
C122  value 0.1 uF  Voltage - Rated: 25V  [0402L_cap]  (hidden comment: GRT155R71E104KE01J)
C123  value 0.1 uF  Voltage - Rated: 25V  [0402L_cap]  (hidden comment: 04023D104KAT2A)
C124  value 0.1 uF  Voltage - Rated: 25V  [0402L_cap]  (hidden comment: 04023D104KAT2A)
C125  value 0.1 uF  Voltage - Rated: 25V  [0402L_cap]  (hidden comment: 04023D104KAT2A)
C126  value 0.1 uF  Voltage - Rated: 25V  [0402L_cap]  (hidden comment: 04023D104KAT2A)
C127  value 0.1 uF  Voltage - Rated: 25V  [0402L_cap]  (hidden comment: 04023D104KAT2A)
C128  value 0.1 uF  Voltage - Rated: 25V  [0402L_cap]  (hidden comment: 04023D104KAT2A)
C129  value 18 pF  Voltage - Rated: 25V  [0201_cap]  (hidden comment: GJM0336C1E180JB01J)
C130  value 18 pF  Voltage - Rated: 25V  [0201_cap]  (hidden comment: GJM0336C1E180JB01J)
C131  value 0.1 uF  Voltage - Rated: 25V  [0402L_cap]  (hidden comment: GRT155R71E104KE01J)
C132  value 4.7 uF  Voltage - Rated: 10V  [0402L_cap]  (hidden comment: C1005X5R1A475K050BC)
C133  value 1 uF  Voltage - Rated: 25V  [0402L_cap]  (hidden comment: CM05X5R105K25AH)
C134  value 0.1 uF  Voltage - Rated: 25V  [0402L_cap]  (hidden comment: GRT155R71E104KE01J)
D4  Text1: USB  [LED_LTST-C190-Green]  (hidden comment: LTST-C191TGKT)
FB7  DCR: 120 mΩ  [0402L]  (hidden comment: NFZ15SG151SN11D)
FB8  DCR: 120 mΩ  [0402L]  (hidden comment: NFZ15SG151SN11D)
J3  USB4105-GF-A  [FP-USB4105-GF-A_CONN_USB_9MM58_7MM53-MFG]
R97  value 10 kΩ  [0402L]  (hidden comment: ERJ-2RKF1002X)
R98  value 4.7 kΩ  [0402L]  (hidden comment: ERJ-2RKF4701X)
R99  value 0 Ω  [0201]  (hidden comment: ERJ-1GN0R00C)
R100  value 10 kΩ  [0402L]  (hidden comment: ERJ-2RKF1002X)
R101  value 4.7 kΩ  [0402L]  (hidden comment: ERJ-2RKF4701X)
R102  value 0 Ω  [0201]  (hidden comment: ERJ-1GN0R00C)
R103  value 100 Ω  [0402L]  (hidden comment: ERJ-2RKF1000X)
R104  value 0 Ω  [0805L]  (hidden comment: ERJ-6GEY0R00V)
R105  value 10 Ω  [0402L]  (hidden comment: ERJ-2GEJ100X)
R106  value 10 Ω  [0402L]  (hidden comment: ERJ-2GEJ100X)
R107  value 0 Ω  [0201]  (hidden comment: ERJ-1GN0R00C)
R108  value 2.2 kΩ  [0402L]  (hidden comment: ERJ-2GEJ222X)
R109  value 10 Ω  [0402L]  (hidden comment: ERJ-2GEJ100X)
R110  value 12 kΩ  [0402L]  (hidden comment: ERJ-2GEJ123X)
R111  value 10 kΩ  [0402L]  (hidden comment: ERJ-2RKF1002X)
R112  value 10 kΩ  [0402L]  (hidden comment: ERJ-2RKF1002X)
R113  value 10 kΩ  [0402L]  (hidden comment: ERJ-2RKF1002X)
R114  value 2.2 kΩ  [0402L]  (hidden comment: ERJ-2GEJ222X)
R115  value 0 Ω  [0805L]  (hidden comment: ERJ-6GEY0R00V)
R116  value 0 Ω  [0805L]  (hidden comment: ERJ-6GEY0R00V)
R117  value 2.2 kΩ  [0402L]  (hidden comment: ERJ-2GEJ222X)
U36  SN74LVC2G125DCUT  [DCU0008A]  (value not drawn)  (parts A,B,C of 3)
U37  FT4232HL-REEL  [LQFP64-MFG]
U38  SN74AVC4T774BQB  Text1: DIR: Low = B→A, High = A→B  [BQB0016A-MFG]
U39  SN74AVC4T774BQB  Text1: DIR: Low = B→A, High = A→B  [BQB0016A-MFG]
U40  93LC46B-I/ST  [TSSOP-8]
U41  TLV70233DBV  Text1: 300mA, Vin 2V→5.5V  [DBV0005A]
U42  SN74AVCH2T45DCU  Text1: DIR: Low = B→A, High = A→B  [DCU0008A]
Y1  Text1: 12MHz  [XTAL_ABM3]  (hidden comment: ABM3-12.000MHZ-D2Y-T)

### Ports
CCLK_SHIFT (out, see 17), DIN_SHIFT (out, see 17), DONE_SHIFT (out, see 17), F2F_RST_SHIFT (out, see 18), F2F_SCLK_SHIFT (out, see 17), F2F_SDI_SHIFT (out, see 17), F2F_SDO_SHIFT (in, see 17), F2F_SEN_SHIFT (out, see 17), FTDI_I2C_SCL (out, see 11), FTDI_I2C_SDA (bidir, see 11), PROG_B_SHIFT (out, see 17), USB_SCLK_DAC_3p3 (out, see 12), USB_SCLK_LMK_3p3 (out, see 12), USB_SDI_DAC_3p3 (out, see 12), USB_SDI_LMK_3p3 (out, see 12), USB_SDO_DAC_3p3 (in, see 12), USB_SDO_LMK_3p3 (in, see 12), USB_~{CS}_DAC_3p3 (out, see 12), USB_~{CS}_LMK_3p3 (out, see 12)

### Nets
3p3V_FTDI: C123.2 C124.2 C125.2 C126.2 C127.2 C128.2 FB7.1 FB8.1 R105.2 R111.2 R112.2 R113.2 R115.1 R116.2 U37.20(VCCIO) U37.31(VCCIO) U37.42(VCCIO) U37.50(VREGIN) U37.56(VCCIO) U40.8(VCC)
3p3V_Utility: C113.2 C119.2 C121.2 C131.2 R97.2 R98.1 R100.2 R101.1 R116.1 U36.8(VCC) U38.1(DIR1) U38.2(DIR2) U38.7(DIR3) U38.8(DIR4) U38.16(VCCA) U39.1(DIR1) U39.2(DIR2) U39.8(DIR4) U39.16(VCCA) U42.1(VCCA) U42.5(DIR)
GND: C113.1 C114.1 C115.1 C116.1 C117.1 C118.1 C119.1 C120.1 C121.1 C122.1 C123.1 C124.1 C125.1 C126.1 C127.1 C128.1 C129.1 C130.1 C131.1 C132.1 C133.1 C134.1 J3.1,2,3,4(SHELL) J3.A1,B1(GND) R108.1 R110.1 U36.2(1A) U36.4(GND) U36.5(2A) U37.1(GND) U37.5(GND) U37.10(AGND) U37.11(GND) U37.13(TEST) U37.15(GND) U37.25(GND) U37.35(GND) U37.47(GND) U37.51(GND) U38.9(~{OE}) U38.10(GND) U38.17(Thermal_Pad) U39.7(DIR3) U39.9(~{OE}) U39.10(GND) U39.17(Thermal_Pad) U40.5(VSS) U41.2(GND) U42.4(GND)
USB_5V: C132.2 D4.1(A) R104.2 R117.2 U41.1(IN)
VADJ: C120.2 C122.2 C134.2 U38.15(VCCB) U39.15(VCCB) U42.8(VCCB)
CCLK_SHIFT: U38.14(B1) ; port CCLK_SHIFT
DIN_SHIFT: U38.13(B2) ; port DIN_SHIFT
DONE_SHIFT: U38.11(B4) ; port DONE_SHIFT
F2F_RST_SHIFT: U42.7(B1) ; port F2F_RST_SHIFT
F2F_SCLK_SHIFT: U39.14(B1) ; port F2F_SCLK_SHIFT
F2F_SDI_SHIFT: U39.11(B4) ; port F2F_SDI_SHIFT
F2F_SDO_SHIFT: U39.12(B3) ; port F2F_SDO_SHIFT
F2F_SEN_SHIFT: U39.13(B2) ; port F2F_SEN_SHIFT
FTDI_I2C_SCL: R98.2 U36.3(2Y) ; port FTDI_I2C_SCL
PROG_B_SHIFT: U38.12(B3) ; port PROG_B_SHIFT
USB_~{CS}_DAC_3p3: U37.19(ADBUS3) ; port USB_~{CS}_DAC_3p3
USB_~{CS}_LMK_3p3: U37.54(DDBUS3) ; port USB_~{CS}_LMK_3p3
USB_I2C_SCL: R97.1 R102.2 U36.7(2~{OE})
USB_I2C_SDAr: R101.2 R103.2 U37.28(BDBUS2) ; port FTDI_I2C_SDA
USB_I2C_SDAw: R100.1 U36.1(1~{OE}) U37.27(BDBUS1)
USB_SCLK_DAC_3p3: R99.2 ; port USB_SCLK_DAC_3p3
USB_SCLK_LMK_3p3: R107.2 ; port USB_SCLK_LMK_3p3
USB_SDI_DAC_3p3: U37.17(ADBUS1) ; port USB_SDI_DAC_3p3
USB_SDI_LMK_3p3: U37.52(DDBUS1) ; port USB_SDI_LMK_3p3
USB_SDO_DAC_3p3: U37.18(ADBUS2) ; port USB_SDO_DAC_3p3
USB_SDO_LMK_3p3: U37.53(DDBUS2) ; port USB_SDO_LMK_3p3
VCORE: C118.2 U37.12(VCORE) U37.37(VCORE) U37.49(VREGOUT) U37.64(VCORE)
NetC114_2: C114.2 C115.2 FB7.2 U37.9(VPLL)
NetC116_2: C116.2 C117.2 FB8.2 U37.4(VPHY)
NetC129_2: C129.2 U37.2(OSCI) Y1.1(OSC1)
NetC130_2: C130.2 U37.3(OSCO) Y1.2(OSC2)
NetC133_2: C133.2 R115.2 U41.5(OUT)
NetD4_2: D4.2(K) R108.2
NetJ3_A4,B4: J3.A4,B4(VBUS) R104.1
NetJ3_A6: J3.A6(1_D+) J3.B6(2_D+) R109.1
NetJ3_A7: J3.A7(1_D-) J3.B7(2_D-) R106.1
NetR99_1: R99.1 U37.16(ADBUS0)
NetR102_1: R102.1 U37.26(BDBUS0)
NetR103_1: R103.1 U36.6(1Y)
NetR105_1: R105.1 U37.14(~{RESET})
NetR106_2: R106.2 U37.7(DM)
NetR107_1: R107.1 U37.48(DDBUS0)
NetR109_2: R109.2 U37.8(DP)
NetR110_2: R110.2 U37.6(REF)
NetR111_1: R111.1 U37.62(EECLK) U40.2(CLK)
NetR112_1: R112.1 R114.1 U40.4(DO)
NetR113_1: R113.1 U37.63(EECS) U40.1(CS)
NetR114_2: R114.2 U37.61(EEDATA) U40.3(DI)
NetR117_1: R117.1 U41.3(EN)
NetU37_34: U37.34(BDBUS7) U42.2(A1)
NetU37_38: U37.38(CDBUS0) U38.3(A1)
NetU37_39: U37.39(CDBUS1) U38.4(A2)
NetU37_40: U37.40(CDBUS2) U38.5(A3)
NetU37_41: U37.41(CDBUS3) U38.6(A4)
NetU37_43: U37.43(CDBUS4) U39.3(A1)
NetU37_44: U37.44(CDBUS5) U39.4(A2)
NetU37_45: U37.45(CDBUS6) U39.5(A3)
NetU37_46: U37.46(CDBUS7) U39.6(A4)

Not connected (* = marked no-connect by the designer): J3 A5(CC1)* A8(SBU1)* B5(CC2)* B8(SBU2)*; U37 21(ADBUS4) 22(ADBUS5) 23(ADBUS6) 24(ADBUS7) 29(BDBUS3) 30(BDBUS4) 32(BDBUS5) 33(BDBUS6) 36(~{SUSPEND})* 55(DDBUS4) 57(DDBUS5) 58(DDBUS6) 59(DDBUS7) 60(~{PWREN})*; U40 6(NC)* 7(NC)*; U41 4(NC)*; U42 3(A2)* 6(B2)*

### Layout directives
net class Power; net class GenPwr: NetC133_2, USB_5V

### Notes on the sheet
- DAC SPI
- FTDI → I2C BUS
- (near C120) FTDI → FPGA Programming
- LMK SPI
- FTDI → FPGA SPI
- (near C134) FTDI → FPGA CTRL

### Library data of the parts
C113 C119-C122 C131 C134 = capcc09401: as C80 on sheet Power LDO 0p8V Analog
C114 C116 C132 = capcc03298: CAP CER 4.7UF 10V X5R 0402; Manufacturer: TDK Corporation; CompType: Capacitor Ceramic; Tolerance: ±10%; SizeX_mm: 1; SizeY_mm: 0.5; SizeZ_mm: 0.65
C115 C117 C123-C128 = capcc01256: CAP CER 0.1UF 25V X5R 0402; Manufacturer: KYOCERA AVX; CompType: Capacitor Ceramic; Tolerance: ±10%; SizeX_mm: 1; SizeY_mm: 0.5; SizeZ_mm: 0.55
C118 = capcc03130: CAP CER 3.3UF 10V X5R 0603; Manufacturer: TDK Corporation; CompType: Capacitor Ceramic; Tolerance: ±10%; SizeX_mm: 1.6; SizeY_mm: 0.8; SizeZ_mm: 0.9
C129 C130 = capcc08580: CAP CER 18PF 25V C0H 0201; Manufacturer: Murata Electronics; CompType: Capacitor Ceramic; Tolerance: ±5%; SizeX_mm: 0.6; SizeY_mm: 0.3; SizeZ_mm: 0.33
C133 = capcc02805: CAP CER 1UF 25V X5R 0402; Manufacturer: KYOCERA AVX; CompType: Capacitor Ceramic; Tolerance: ±10%; SizeX_mm: 1; SizeY_mm: 0.5; SizeZ_mm: 0.55
D4 = cmp00247: LED GREEN CLEAR CHIP SMD; Manufacturer: Lite-On Inc.; Current Rating (Amps): 20mA; Voltage - Forward (Vf) (Typ): 3.2V; SizeX_mm: 1.6; SizeY_mm: 0.8; SizeZ_mm: 0.65
FB7 FB8 = dcp00209: 0402 (1005) 150OHM (TYP.) 1000MA; Manufacturer: Murata Electronics; Current: 1A
J3 = USB4105-GF-A: USB - C (Type - C) USB 2.0 Receptacle Connector 24 Position Surface Mount, Right Angle; Through Hole; Manufacturer: GCT; CompType: USB C
R97 R100 R111-R113 = RSMD040200314: as R68 on sheet Power LDO 0p8V Analog
R98 R101 = RSMD040202594: RES SMD 4.7K OHM 1% 1/10W 0402; Manufacturer: Panasonic Electronic Components; CompType: Resistor SMD; Power (Watts): 0.1W, 1/10W; Temperature Coefficient: ±100ppm/°C; SizeX_mm: 1; SizeY_mm: 0.5; SizeZ_mm: 0.4
R99 R102 R107 = RSMD020101699: RES SMD 0 OHM JUMPER 1/20W 0201; Manufacturer: Panasonic Electronic Components; CompType: Resistor SMD; Power (Watts): 0.05W, 1/20W
R103 = RSMD040200375: RES SMD 100 OHM 1% 1/10W 0402; Manufacturer: Panasonic Electronic Components; CompType: Resistor SMD; Power (Watts): 0.1W, 1/10W; Temperature Coefficient: ±100ppm/°C; SizeX_mm: 1; SizeY_mm: 0.5; SizeZ_mm: 0.4
R104 R115 R116 = RSMD080510615: RES SMD 0 OHM JUMPER 1/8W 0805; Manufacturer: Panasonic Electronic Components; CompType: Resistor SMD; Power (Watts): 0.125W, 1/8W; SizeX_mm: 2; SizeY_mm: 1.25; SizeZ_mm: 0.7
R105 R106 R109 = RSMD040200327: RES SMD 10 OHM 5% 1/10W 0402; Manufacturer: Panasonic Electronic Components; CompType: Resistor SMD; Power (Watts): 0.1W, 1/10W; Temperature Coefficient: ±200ppm/°C; SizeX_mm: 1; SizeY_mm: 0.5; SizeZ_mm: 0.4
R108 R114 R117 = RSMD040201206: RES SMD 2.2K OHM 5% 1/10W 0402; Manufacturer: Panasonic Electronic Components; CompType: Resistor SMD; Power (Watts): 0.1W, 1/10W; Temperature Coefficient: ±200ppm/°C; SizeX_mm: 1; SizeY_mm: 0.5; SizeZ_mm: 0.4
R110 = RSMD040200523: RES SMD 12K OHM 5% 1/10W 0402; Manufacturer: Panasonic Electronic Components; CompType: Resistor SMD; Power (Watts): 0.1W, 1/10W; Temperature Coefficient: ±200ppm/°C; SizeX_mm: 1; SizeY_mm: 0.5; SizeZ_mm: 0.4
U36 = SN74LVC2G125DCUT: Dual Bus Buffer Gate with 3-State Outputs, DCU0008A (VSSOP-8); Manufacturer: Texas Instruments; F @ Nom Voltage(Max)(Mhz): 150; VCC(Min)(V): 1.65; Bits(#): 2; Output Type: CMOS; Technology Family: LVC; Rating: Catalog; tpd @ Nom Voltage(Max)(ns): 9.1,4.8,4.3,3.7; 3-State Output: Yes; Schmitt Trigger: No; Logic: True; Voltage(Nom)(V): 1.8,2.5,3.3,5; Output Drive (IOL/IOH)(Max)(mA): 32/-32; ICC @ Nom Voltage(Max)(mA): 0.01; Input Type: CMOS/TTL; VCC(Max)(V): 5.5; AEC Category: Q200; AEC Qualified: N; CompType: IC; SizeAreaWB_mm2: 12.6; SizeArea_mm2: 6.4; SizeX_mm: 3.2; SizeY_mm: 2.0; SizeZ_mm: 0.9
U37 = cmp00204: USB Interface IC USB HS to Quad UART/ SPI/JTAG/I2C LQFP-6; Manufacturer: FTDI; Alt PartNumber: FT4232HL-TRAY; Symbol Name: SYM-FT4232HL-REEL; CompType: uC
U38 U39 = cmp00170: Translation - Voltage Levels 4-bit dual-supply bus transceiver with 3-state outputs and independent direction control inputs; Manufacturer: Texas Instruments; Alt PartNumber: SN74AXC4T774BQB; CompType: Level Shifter
U40 = cmp00156: 1K Microwire Compatible Serial EEPROM; Manufacturer: Microchip Technology; SymbolCreator: Altium; SizeArea_mm2: 19.2; SizeAreaWB_mm2: 42
U41 = cmp00162: 300-mA, high-PSRR, low-IQ, low-dropout voltage regulator with enable; Manufacturer: Texas Instruments; CompType: LDO
U42 = cmp00175: Dual-Bit Dual-Supply Bus Transceiver With Configurable Voltage Translation And 3-State Outputs; Manufacturer: Texas Instruments; Alt PartNumber: SN74AXCH2T45DCU; CompType: Level Shifter
Y1 = cmp00323: 12 MHz ±20ppm Crystal 18pF 60 Ohms 2-SMD, No Lead; Manufacturer: Abracon LLC; CompType: XO

## Sheet I2C & DAC LVL Shift and MUX.SchDoc: Comms Lvl Shift & Mux
size 431 x 279 mm; Date: Not shown in title block; ApprovedBy: Not shown in title block; CheckedBy: Not shown in title block; Author: Not shown in title block; CompanyName: Not shown in title block; Engineer: Not shown in title block; Organization: Not shown in title block; Address1: Not shown in title block; Address2: Not shown in title block; Address3: Not shown in title block; Address4: Not shown in title block; DocumentNumber: 1; Revision: Use project parameter SCH_Rev; SheetNumber: 11; SheetTotal: 21; PageSetup: Record=PageOptions¦CenterHorizontal=True¦CenterVertical=True¦PrintScale=1.00¦XCorrection=1.00¦YCorrection=1.00¦PrintKind=0¦BorderSize=5000000¦LeftOffset=0¦BottomOffset=0¦Orientation=2¦PaperLength=1000¦PaperWidth=1000¦Scale=100¦PaperSource=15¦PrintQuality=600¦MediaType=1¦DitherType=10¦PaperKind=Letter¦PrintScaleMode=1
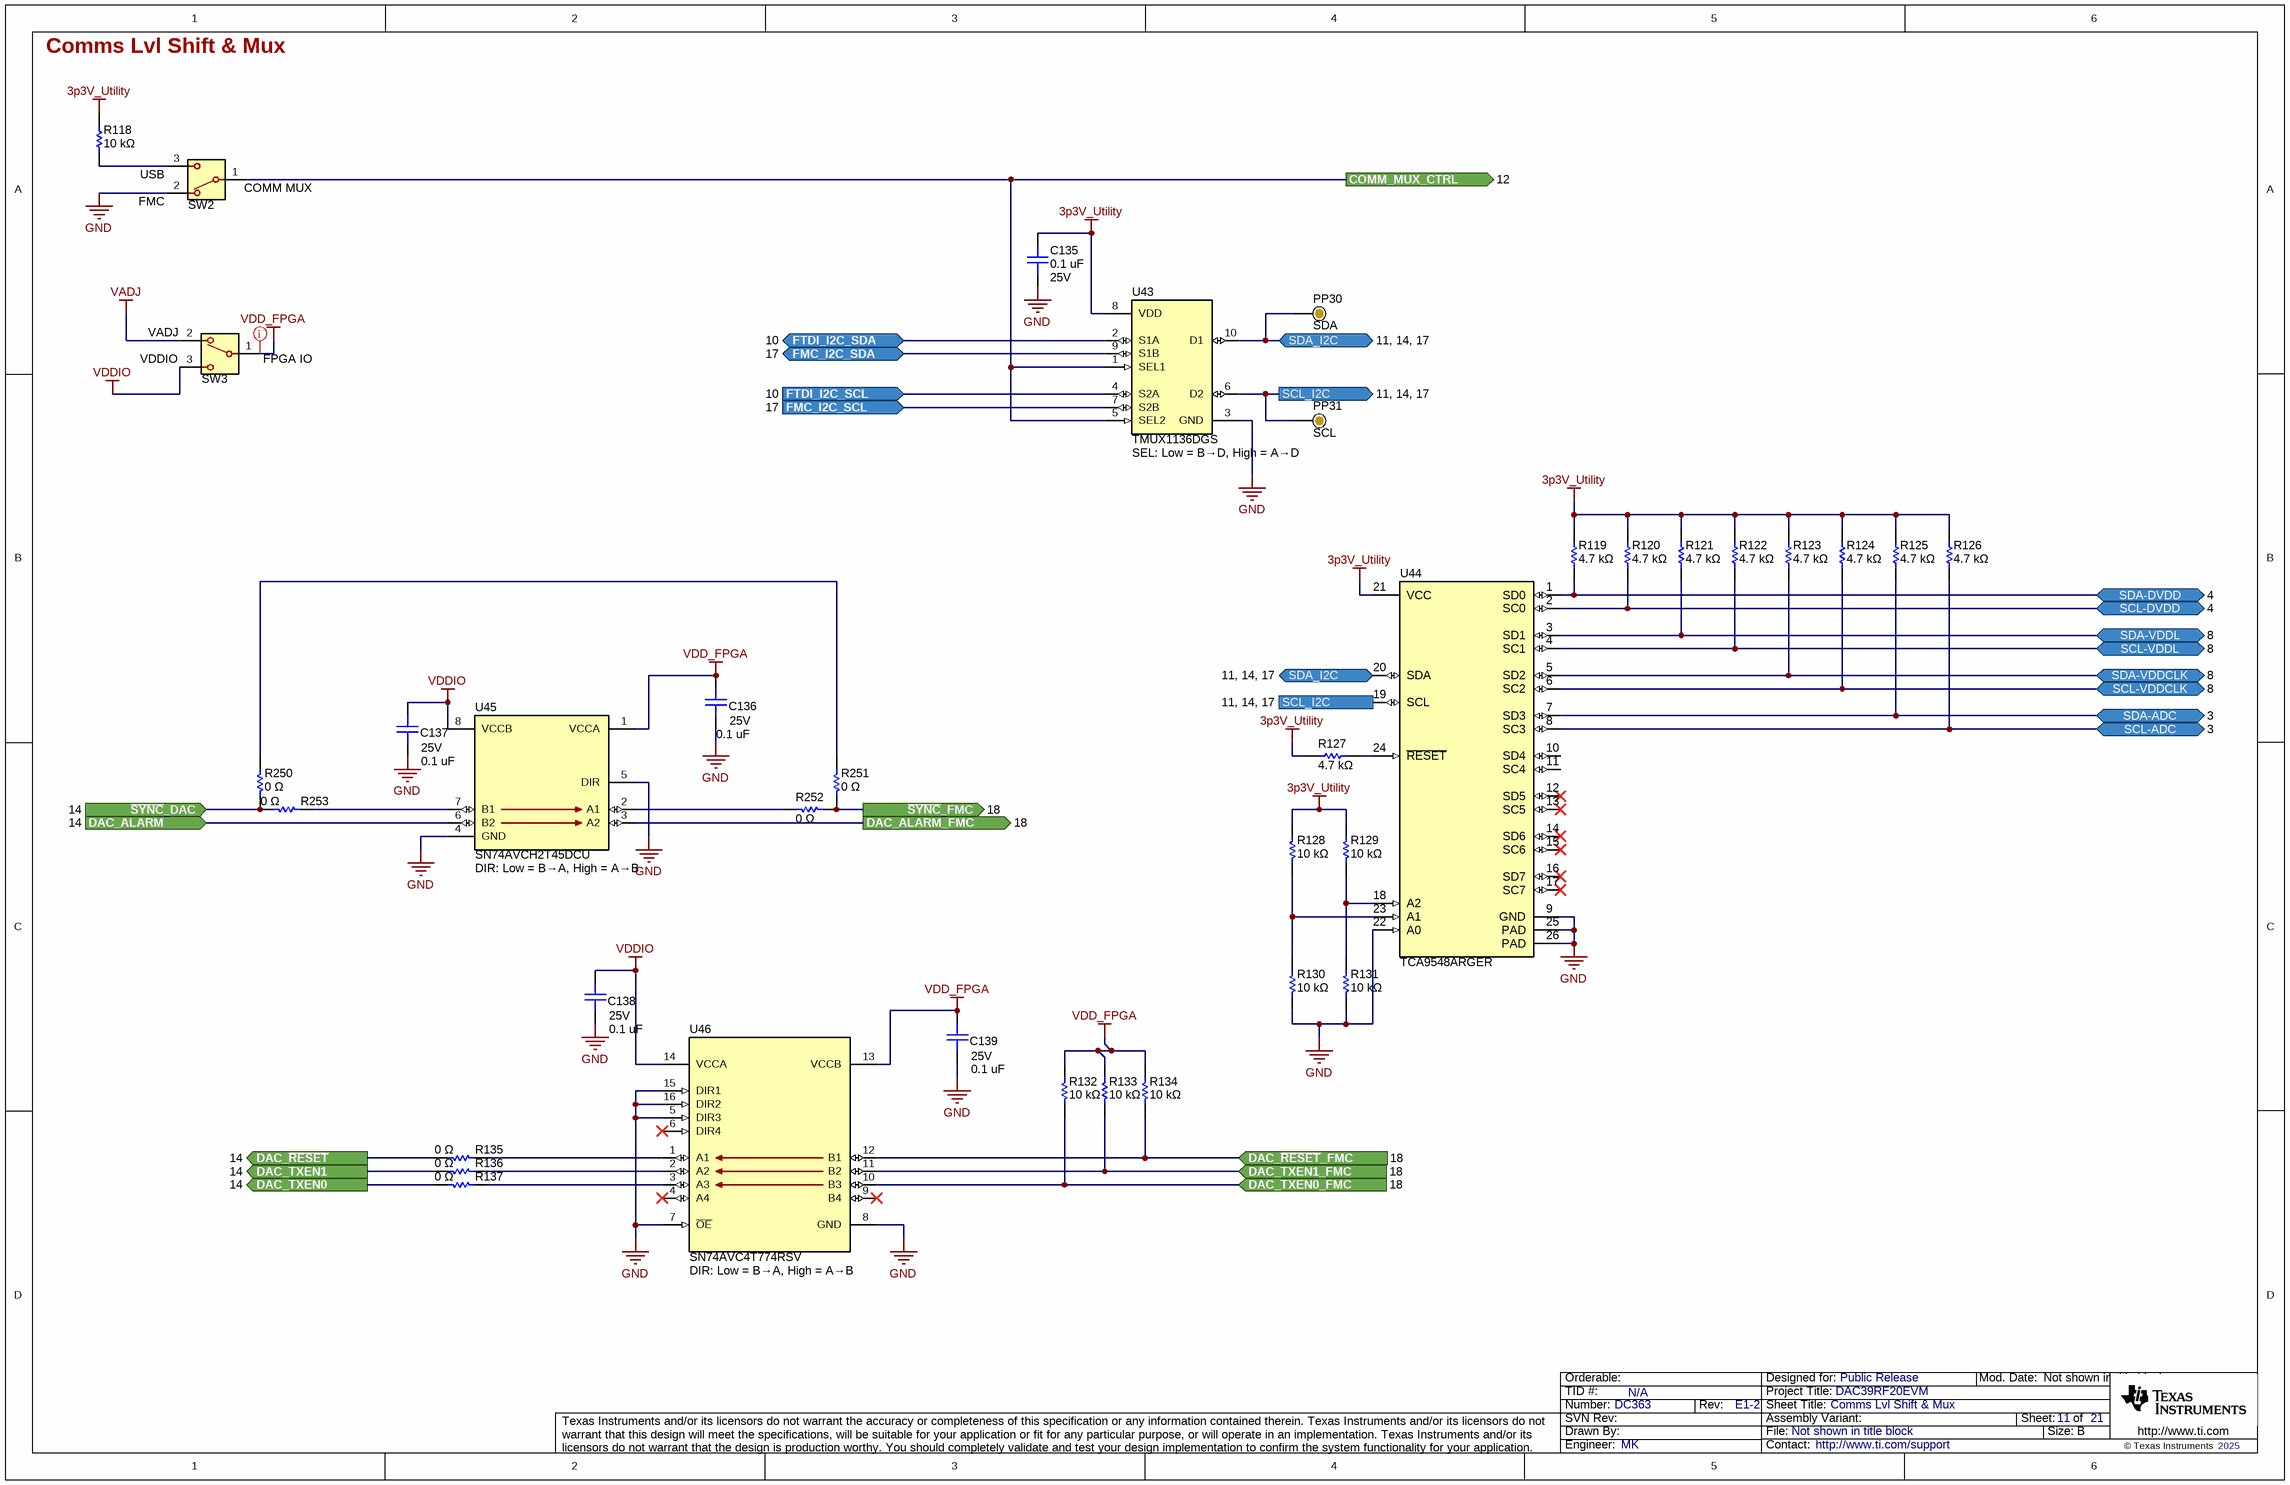
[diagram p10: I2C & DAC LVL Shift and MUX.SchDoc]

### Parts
C135  value 0.1 uF  Voltage - Rated: 25V  [0402L_cap]  (hidden comment: GRT155R71E104KE01J)
C136  value 0.1 uF  Voltage - Rated: 25V  [0402L_cap]  (hidden comment: GRT155R71E104KE01J)
C137  value 0.1 uF  Voltage - Rated: 25V  [0402L_cap]  (hidden comment: GRT155R71E104KE01J)
C138  value 0.1 uF  Voltage - Rated: 25V  [0402L_cap]  (hidden comment: GRT155R71E104KE01J)
C139  value 0.1 uF  Voltage - Rated: 25V  [0402L_cap]  (hidden comment: GRT155R71E104KE01J)
PP30  Text1: SDA  [ProbePoint_TH_40mil]  (hidden comment: Probe Point)  (no BOM)
PP31  Text1: SCL  [ProbePoint_TH_40mil]  (hidden comment: Probe Point)  (no BOM)
R118  value 10 kΩ  [0402L]  (hidden comment: ERJ-2RKF1002X)
R119  value 4.7 kΩ  [0201]  (hidden comment: ERJ-1GNF4701C)
R120  value 4.7 kΩ  [0201]  (hidden comment: ERJ-1GNF4701C)
R121  value 4.7 kΩ  [0201]  (hidden comment: ERJ-1GNF4701C)
R122  value 4.7 kΩ  [0201]  (hidden comment: ERJ-1GNF4701C)
R123  value 4.7 kΩ  [0201]  (hidden comment: ERJ-1GNF4701C)
R124  value 4.7 kΩ  [0201]  (hidden comment: ERJ-1GNF4701C)
R125  value 4.7 kΩ  [0201]  (hidden comment: ERJ-1GNF4701C)
R126  value 4.7 kΩ  [0201]  (hidden comment: ERJ-1GNF4701C)
R127  value 4.7 kΩ  [0201]  (hidden comment: ERJ-1GNF4701C)
R128  value 10 kΩ  [0201]  (hidden comment: ERJ-1GNF1002C)
R129  value 10 kΩ  [0201]  (hidden comment: ERJ-1GNF1002C)
R130  value 10 kΩ  [0201]  (hidden comment: ERJ-1GNF1002C)
R131  value 10 kΩ  [0201]  (hidden comment: ERJ-1GNF1002C)
R132  value 10 kΩ  [0201]  (hidden comment: ERJ-1GNF1002C)
R133  value 10 kΩ  [0201]  (hidden comment: ERJ-1GNF1002C)
R134  value 10 kΩ  [0201]  (hidden comment: ERJ-1GNF1002C)
R135  value 0 Ω  [0201]  (hidden comment: ERJ-1GN0R00C)
R136  value 0 Ω  [0201]  (hidden comment: ERJ-1GN0R00C)
R137  value 0 Ω  [0201]  (hidden comment: ERJ-1GN0R00C)
R250  value 0 Ω  [0201]  (hidden comment: ERJ-1GN0R00C)
R251  value 0 Ω  [0201]  (hidden comment: ERJ-1GN0R00C)
R252  value 0 Ω  [0201]  (hidden comment: ERJ-1GN0R00C)
R253  value 0 Ω  [0201]  (hidden comment: ERJ-1GN0R00C)
SW2  Text1: COMM MUX  Text2: FMC  Text3: USB  [450301014042]  (hidden comment: cmp00353)
SW3  Text1: FPGA IO  Text2: VADJ  Text3: VDDIO  [450301014042]  (hidden comment: cmp00353)
U43  TMUX1136DGS  Text1: SEL: Low = B→D, High = A→D  [DQA0010A]
U44  TCA9548ARGER  [RGE0024M]
U45  SN74AVCH2T45DCU  Text1: DIR: Low = B→A, High = A→B  [DCU0008A]
U46  SN74AVC4T774RSV  Text1: DIR: Low = B→A, High = A→B  [RSV0016A]

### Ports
COMM_MUX_CTRL (out, see 12), DAC_ALARM (in, see 14), DAC_ALARM_FMC (out, see 18), DAC_TXEN0 (out, see 14), DAC_TXEN0_FMC (in, see 18), DAC_TXEN1 (out, see 14), DAC_TXEN1_FMC (in, see 18), DAC_~{RESET} (out, see 14), DAC_~{RESET}_FMC (in, see 18), FMC_I2C_SCL (in, see 17), FMC_I2C_SDA (bidir, see 17), FTDI_I2C_SCL (in, see 10), FTDI_I2C_SDA (bidir, see 10), SCL-ADC (bidir, see 3), SCL-DVDD (bidir, see 4), SCL-VDDCLK (bidir, see 8), SCL-VDDL (bidir, see 8), SCL_I2C (out, see 11, 14, 17), SDA-ADC (bidir, see 3), SDA-DVDD (bidir, see 4), SDA-VDDCLK (bidir, see 8), SDA-VDDL (bidir, see 8), SDA_I2C (bidir, see 11, 14, 17), ~{SYNC}_DAC (in, see 14), ~{SYNC}_FMC (out, see 18)

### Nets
3p3V_Utility: C135.2 R118.2 R119.2 R120.2 R121.2 R122.2 R123.2 R124.2 R125.2 R126.2 R127.2 R128.1 R129.1 U43.8(VDD) U44.21(VCC)
GND: C135.1 C136.2 C137.2 C138.2 C139.2 R130.2 R131.2 SW2.2(COMM) U43.3(GND) U44.9(GND) U44.22(A0) U44.25(PAD) U44.26(PAD) U45.4(GND) U45.5(DIR) U46.5(DIR3) U46.7(~{OE}) U46.8(GND) U46.15(DIR1) U46.16(DIR2)
VADJ: SW3.2(COMM)
VDD_FPGA: C136.1 C139.1 R132.1 R133.1 R134.1 SW3.1 U45.1(VCCA) U46.13(VCCB)
VDDIO: C137.1 C138.1 SW3.3 U45.8(VCCB) U46.14(VCCA)
COMM_MUX_CTRL: SW2.1 U43.1(SEL1) U43.5(SEL2) ; port COMM_MUX_CTRL
DAC_ALARM: U45.6(B2) ; port DAC_ALARM
DAC_ALARM_FMC: U45.3(A2) ; port DAC_ALARM_FMC
DAC_~{RESET}: R135.2 ; port DAC_~{RESET}
DAC_~{RESET}_FMC: R134.2 U46.12(B1) ; port DAC_~{RESET}_FMC
DAC_TXEN0: R137.2 ; port DAC_TXEN0
DAC_TXEN0_FMC: R132.2 U46.10(B3) ; port DAC_TXEN0_FMC
DAC_TXEN1: R136.2 ; port DAC_TXEN1
DAC_TXEN1_FMC: R133.2 U46.11(B2) ; port DAC_TXEN1_FMC
FMC_I2C_SCL: U43.7(S2B) ; port FMC_I2C_SCL
FMC_I2C_SDA: U43.9(S1B) ; port FMC_I2C_SDA
FTDI_I2C_SCL: U43.4(S2A) ; port FTDI_I2C_SCL
~{SYNC}_DAC: R250.2 R253.2 ; port ~{SYNC}_DAC
~{SYNC}_FMC: R251.2 R252.2 ; port ~{SYNC}_FMC
SCL-ADC: R126.1 U44.8(SC3) ; port SCL-ADC
SCL-DVDD: R120.1 U44.2(SC0) ; port SCL-DVDD
SCL-VDDCLK: R124.1 U44.6(SC2) ; port SCL-VDDCLK
SCL-VDDL: R122.1 U44.4(SC1) ; port SCL-VDDL
SCL_I2C: PP31.1 U43.6(D2) U44.19(SCL) ; port SCL_I2C
SDA-ADC: R125.1 U44.7(SD3) ; port SDA-ADC
SDA-DVDD: R119.1 U44.1(SD0) ; port SDA-DVDD
SDA-VDDCLK: R123.1 U44.5(SD2) ; port SDA-VDDCLK
SDA-VDDL: R121.1 U44.3(SD1) ; port SDA-VDDL
SDA_I2C: PP30.1 U43.10(D1) U44.20(SDA) ; port SDA_I2C
USB_I2C_SDAr: U43.2(S1A) ; port FTDI_I2C_SDA
NetR118_1: R118.1 SW2.3
NetR127_1: R127.1 U44.24(~{RESET})
NetR128_2: R128.2 R130.1 U44.23(A1)
NetR129_2: R129.2 R131.1 U44.18(A2)
NetR135_1: R135.1 U46.1(A1)
NetR136_1: R136.1 U46.2(A2)
NetR137_1: R137.1 U46.3(A3)
NetR250_1: R250.1 R251.1
NetR252_1: R252.1 U45.2(A1)
NetR253_1: R253.1 U45.7(B1)

Not connected (* = marked no-connect by the designer): U44 10(SD4) 11(SC4) 12(SD5)* 13(SC5)* 14(SD6)* 15(SC6)* 16(SD7)* 17(SC7)*; U46 4(A4)* 6(DIR4)* 9(B4)*

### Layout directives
net class Power; net class GenPwr: VDD_FPGA

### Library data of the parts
C135 = capcc09401: as C80 on sheet Power LDO 0p8V Analog
C136-C139 = capcc09401: CAP CER 0.1UF 25V X7R 0402; Manufacturer: Murata; SizeZ_mm: 0.7; SizeX_mm: 1; SizeY_mm: 0.5; CompType: Capacitor Ceramic; Tolerance: ±10%
PP30 PP31 = Probe Point: as PP23 on sheet Power LDO N1p8V Analog
R118 = RSMD040200314: as R68 on sheet Power LDO 0p8V Analog
R119-R127 = RSMD020100508: RES SMD 4.7K OHM 1% 1/20W 0201; Manufacturer: Panasonic Electronic Components; CompType: Resistor SMD; Power (Watts): 0.05W, 1/20W; Temperature Coefficient: ±200ppm/°C
R128-R134 = RSMD020100762: RES SMD 10K OHM 1% 1/20W 0201; Manufacturer: Panasonic Electronic Components; CompType: Resistor SMD; Power (Watts): 0.05W, 1/20W; Temperature Coefficient: ±200ppm/°C
R135-R137 R250-R253 = RSMD020101699: as R99 on sheet USB Control FTDI
SW2 SW3 = cmp00353: Switch Slide SPDT 12V, 500mA; Manufacturer: Wurth Elektronik
U43 = cmp00307: 5-V low-leakage-current, 2: 1, 2-channel precision analog switch; PartNumber: TMUX1136DQA; Manufacturer: Texas Instruments; CompType: MUX
U44 = TCA9548ARGE: Low-Voltage 8-Channel I2C Switch With Reset, RGE0024C (VQFN-24); Alternate Manufacturer: Texas Instruments; SizeZ_mm: 1.0; SizeY_mm: 4.0; SizeArea_mm2: 16.0; CompType: IC; SizeAreaWB_mm2: 25.0; AEC Category: Q200; SymbolCreator: x0208326
U45 = cmp00175: as U42 on sheet USB Control FTDI
U46 = cmp00171: Translation - Voltage Levels 4-bit dual-supply bus transceiver with 3-state outputs and independent direction control inputs; Manufacturer: Texas Instruments; Alt PartNumber: SN74AXC4T774RSV; CompType: Level Shifter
